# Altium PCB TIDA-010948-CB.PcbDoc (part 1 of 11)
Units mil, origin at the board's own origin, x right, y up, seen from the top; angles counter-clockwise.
Board outline 8100 x 8400 mil, 8 copper layers (L01 - TOP, L02 - GND, L03 - SIG, L04 - GND, L05 - PWR, L06 - SIG, L07 - GND, L08 - BOTTOM), stack 59.656 mil thick; 711 components, 572 nets, 2646 pads, 1325 vias.
Unrouted connection lines stored in the file: 988.
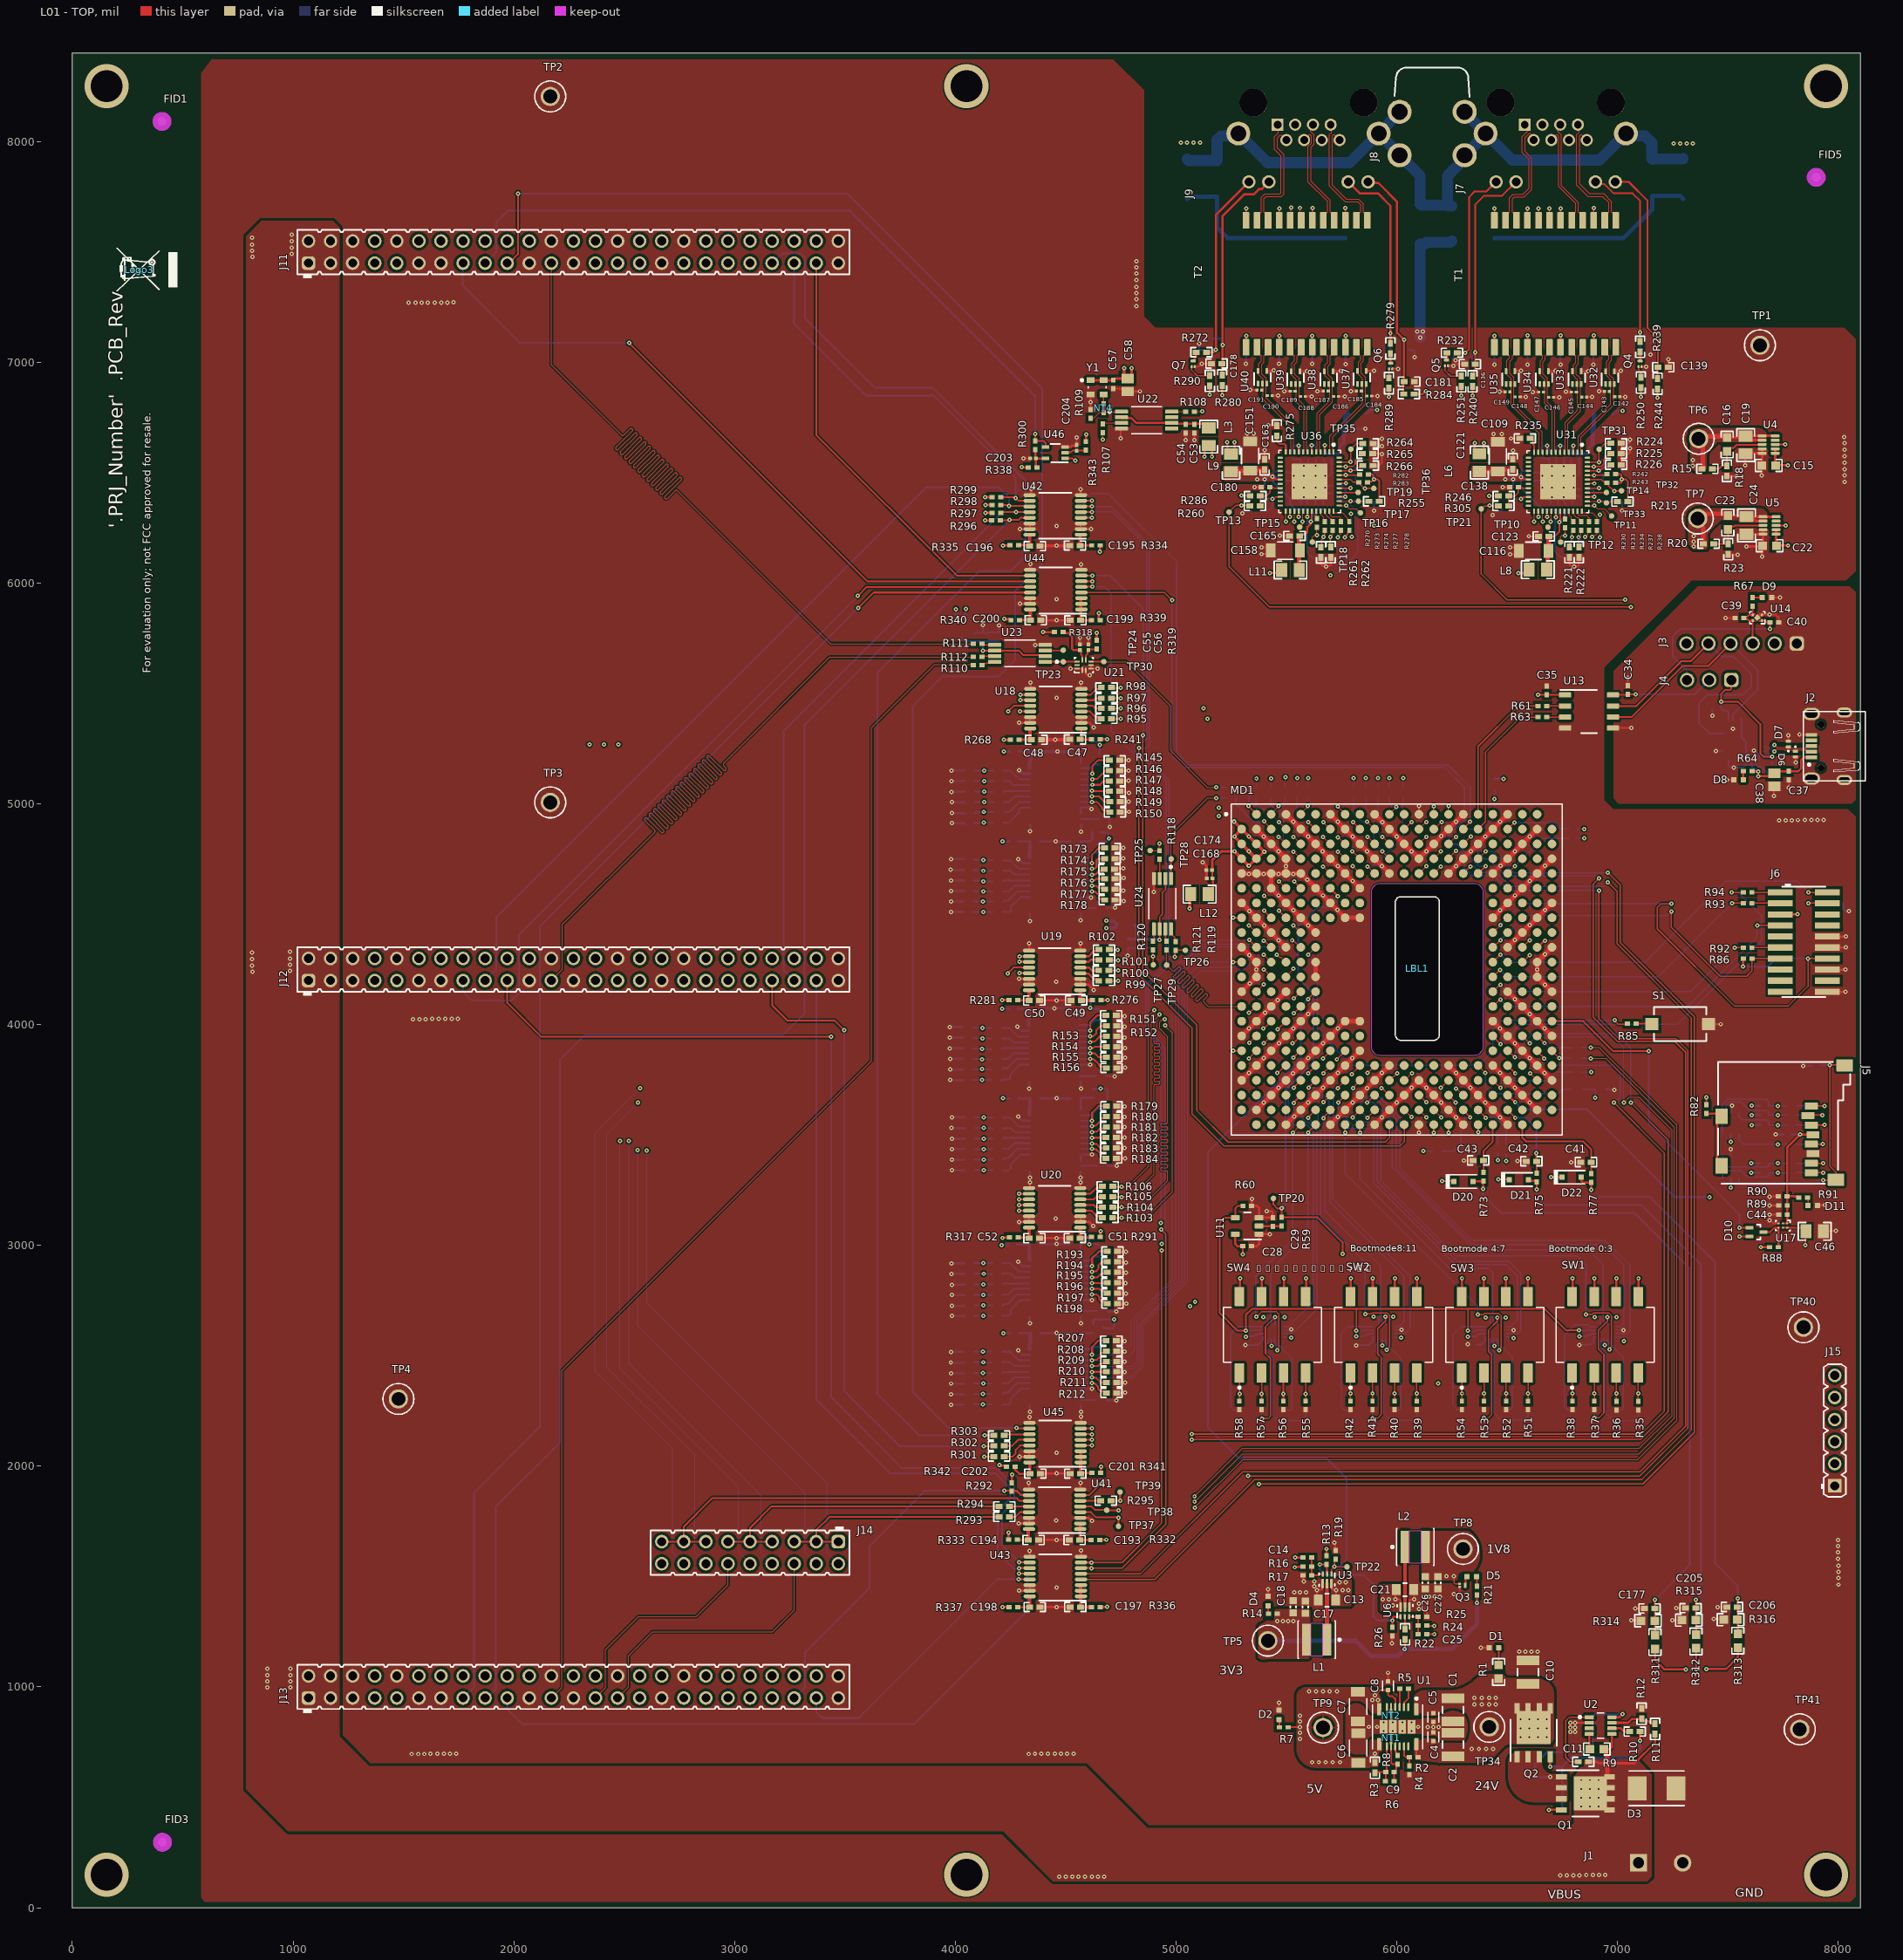
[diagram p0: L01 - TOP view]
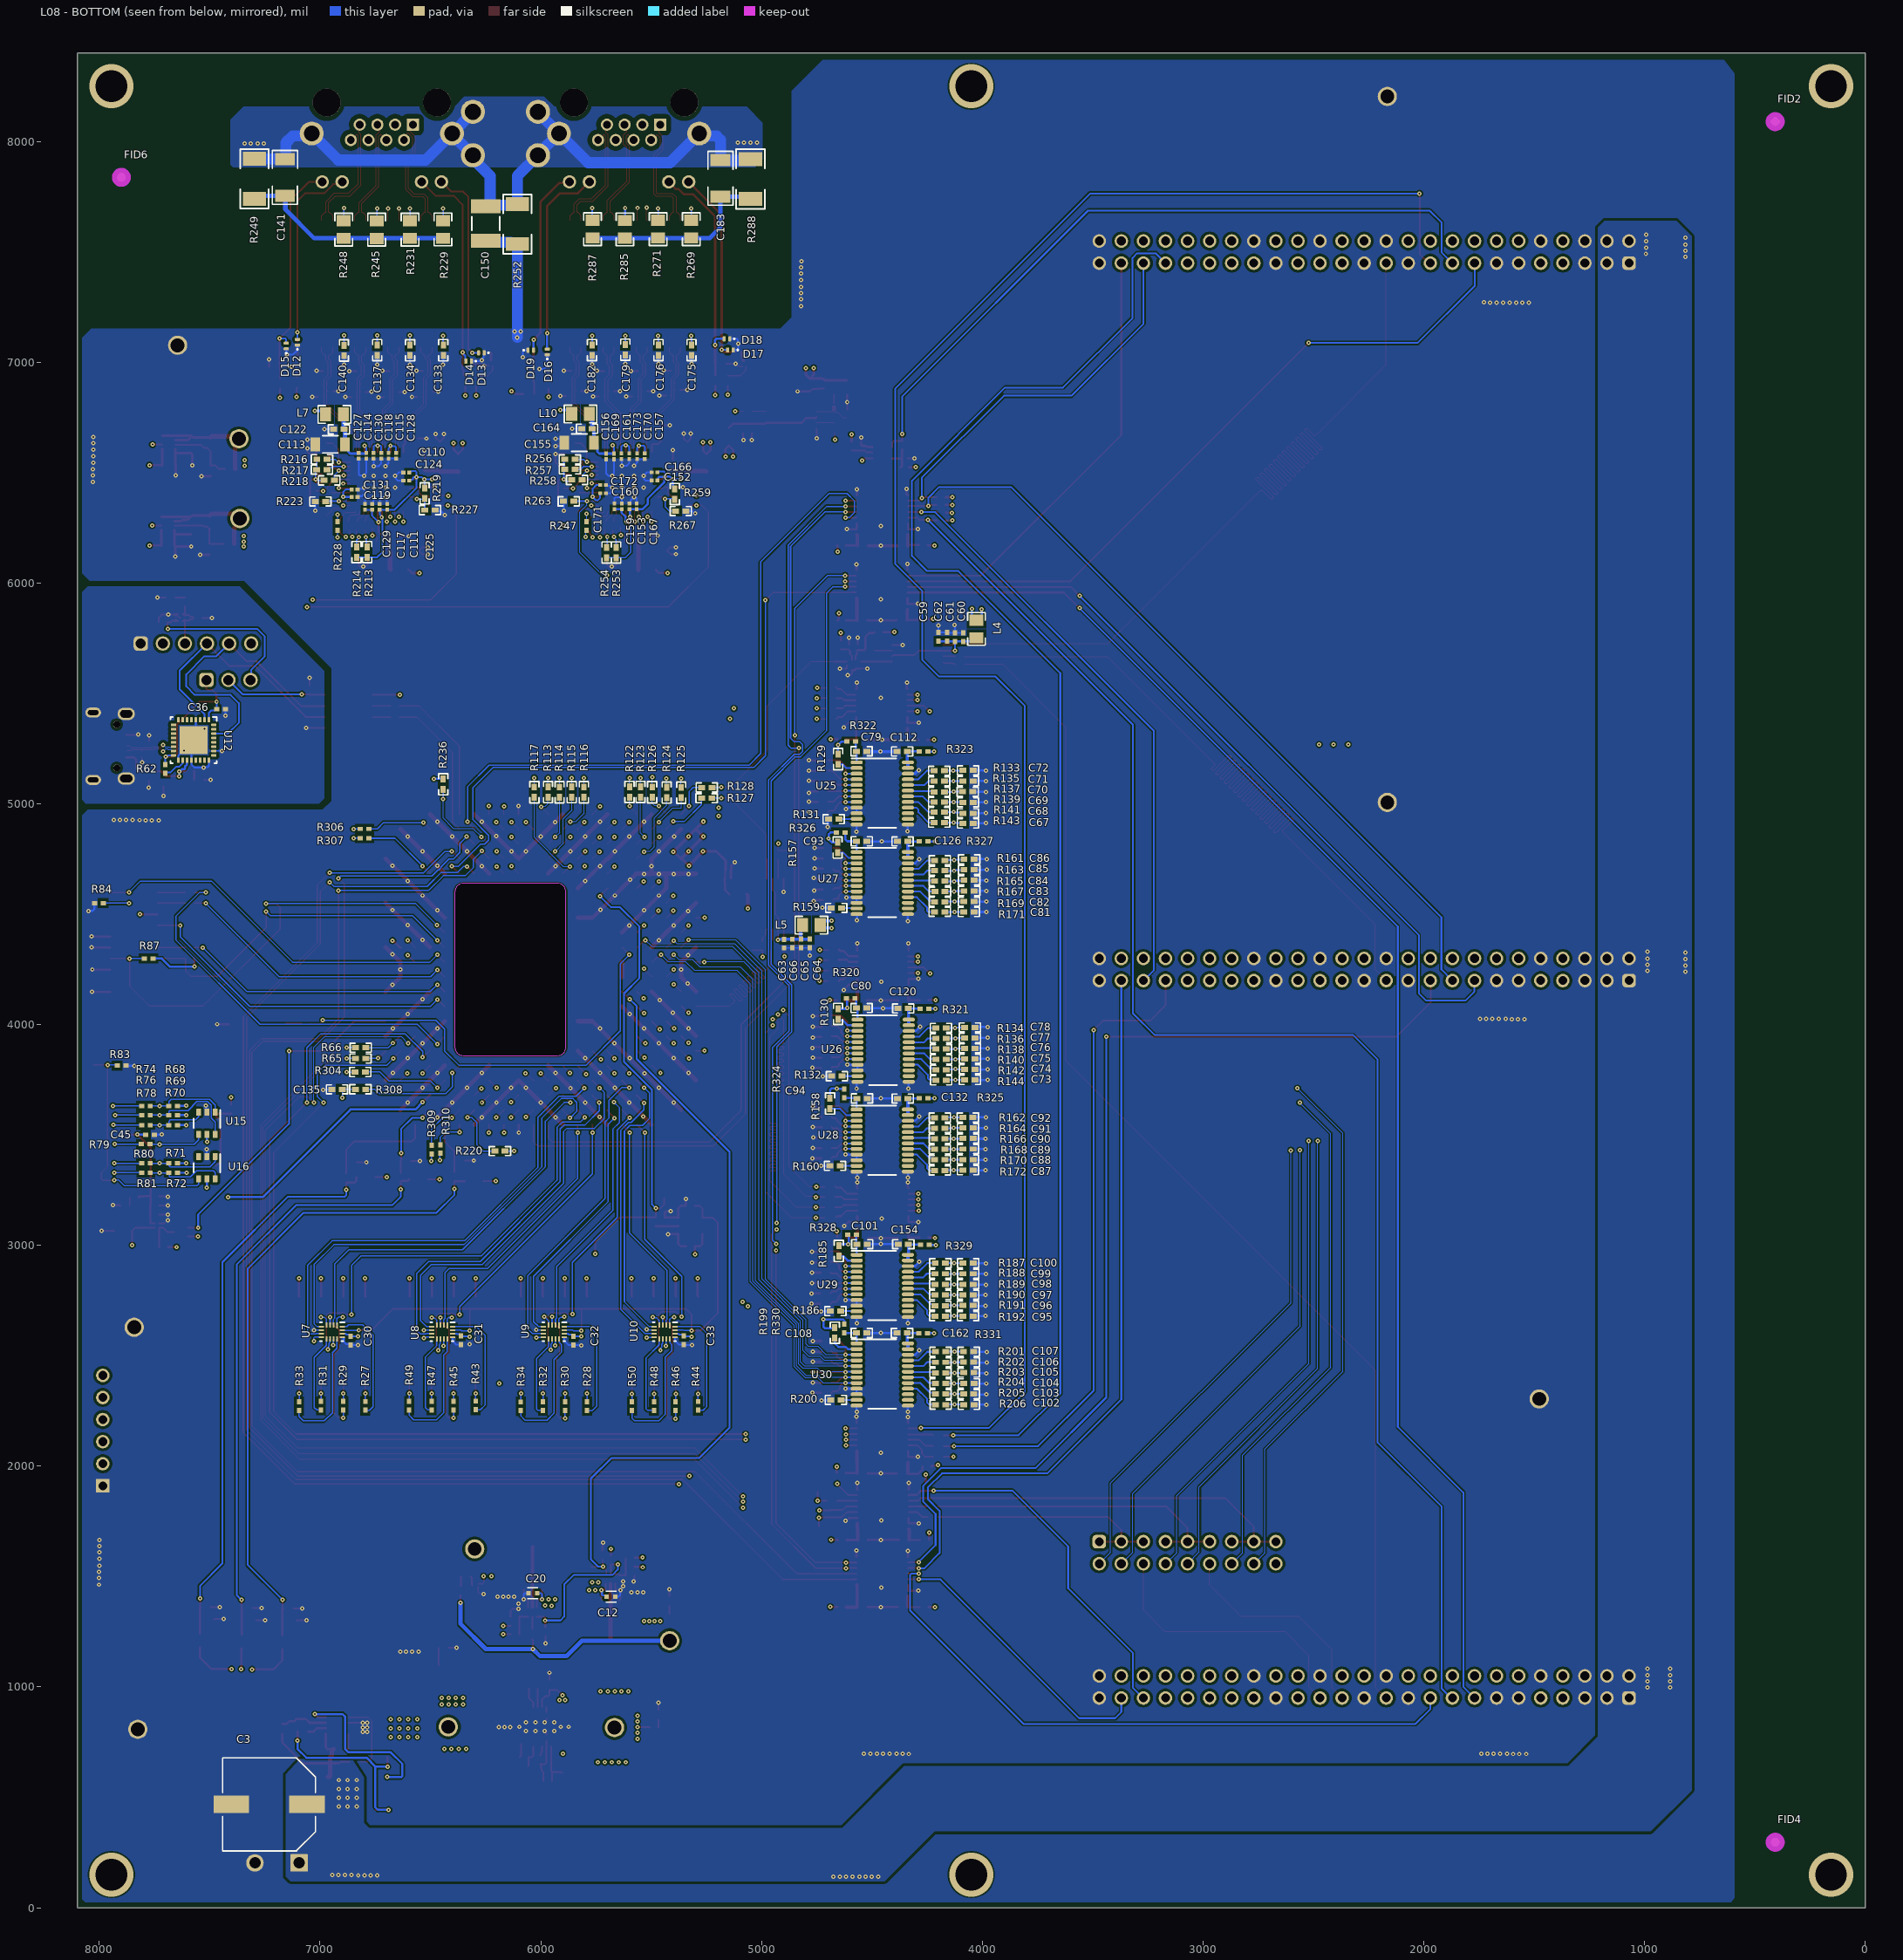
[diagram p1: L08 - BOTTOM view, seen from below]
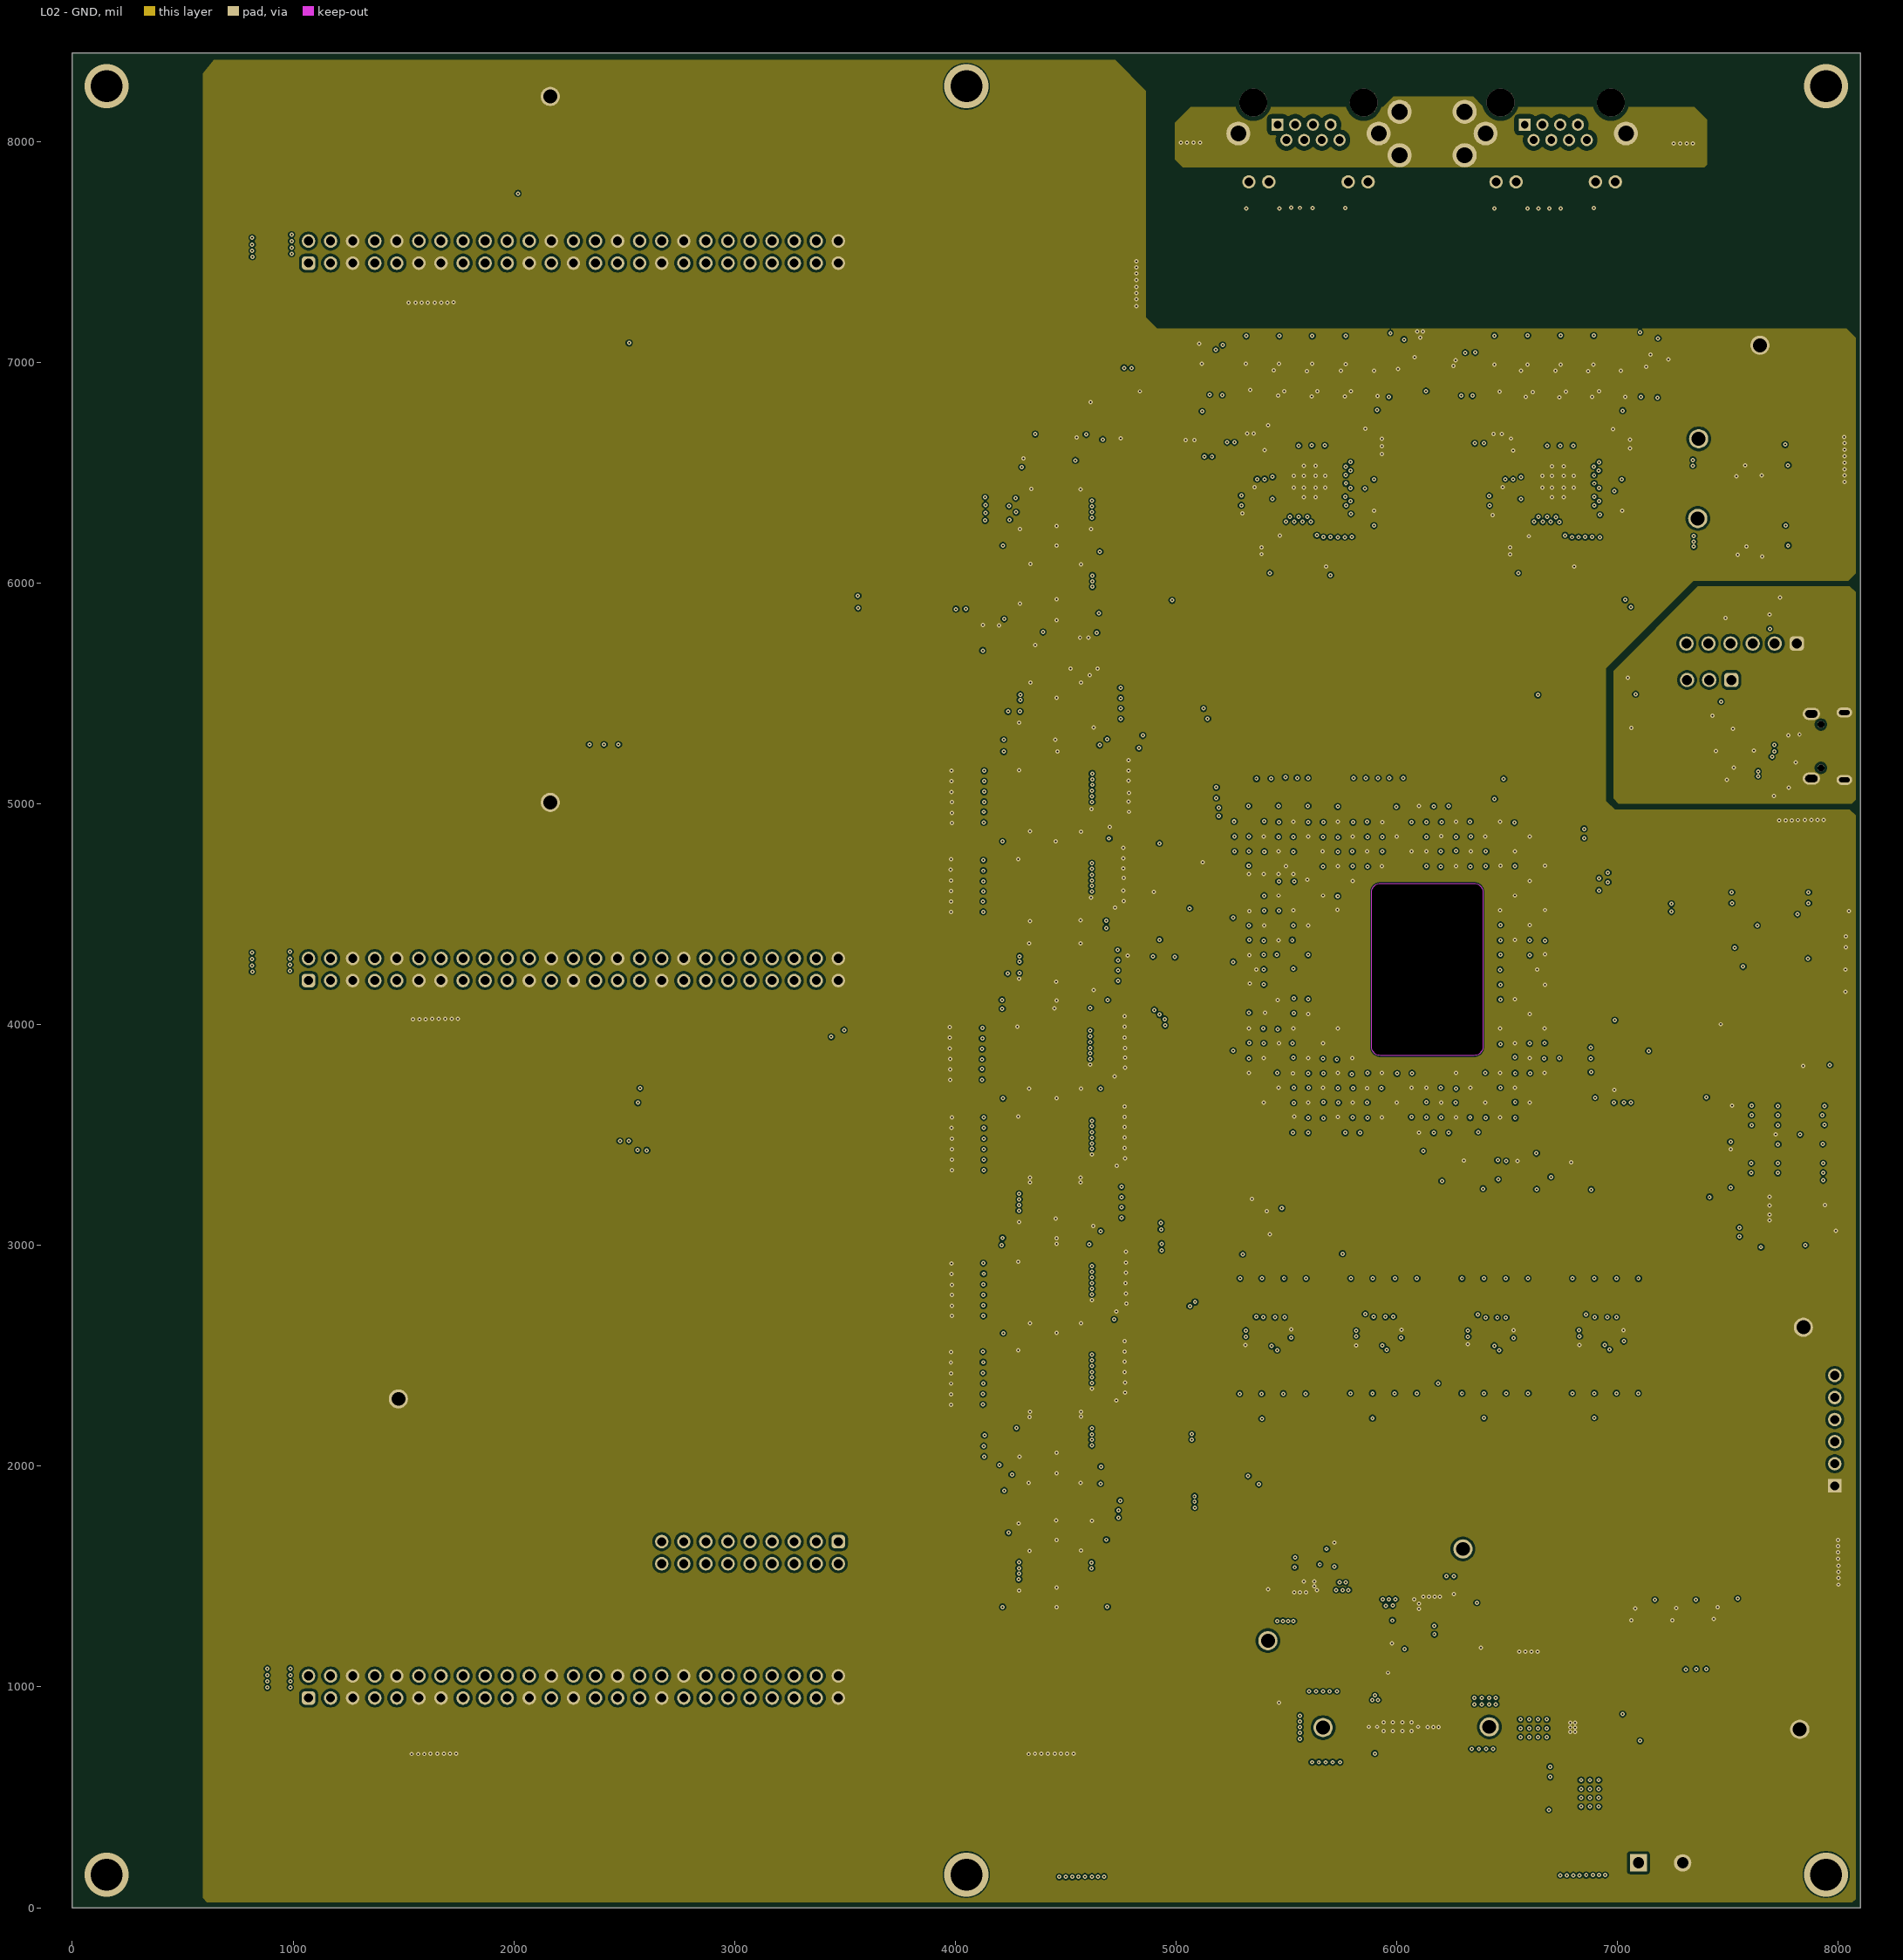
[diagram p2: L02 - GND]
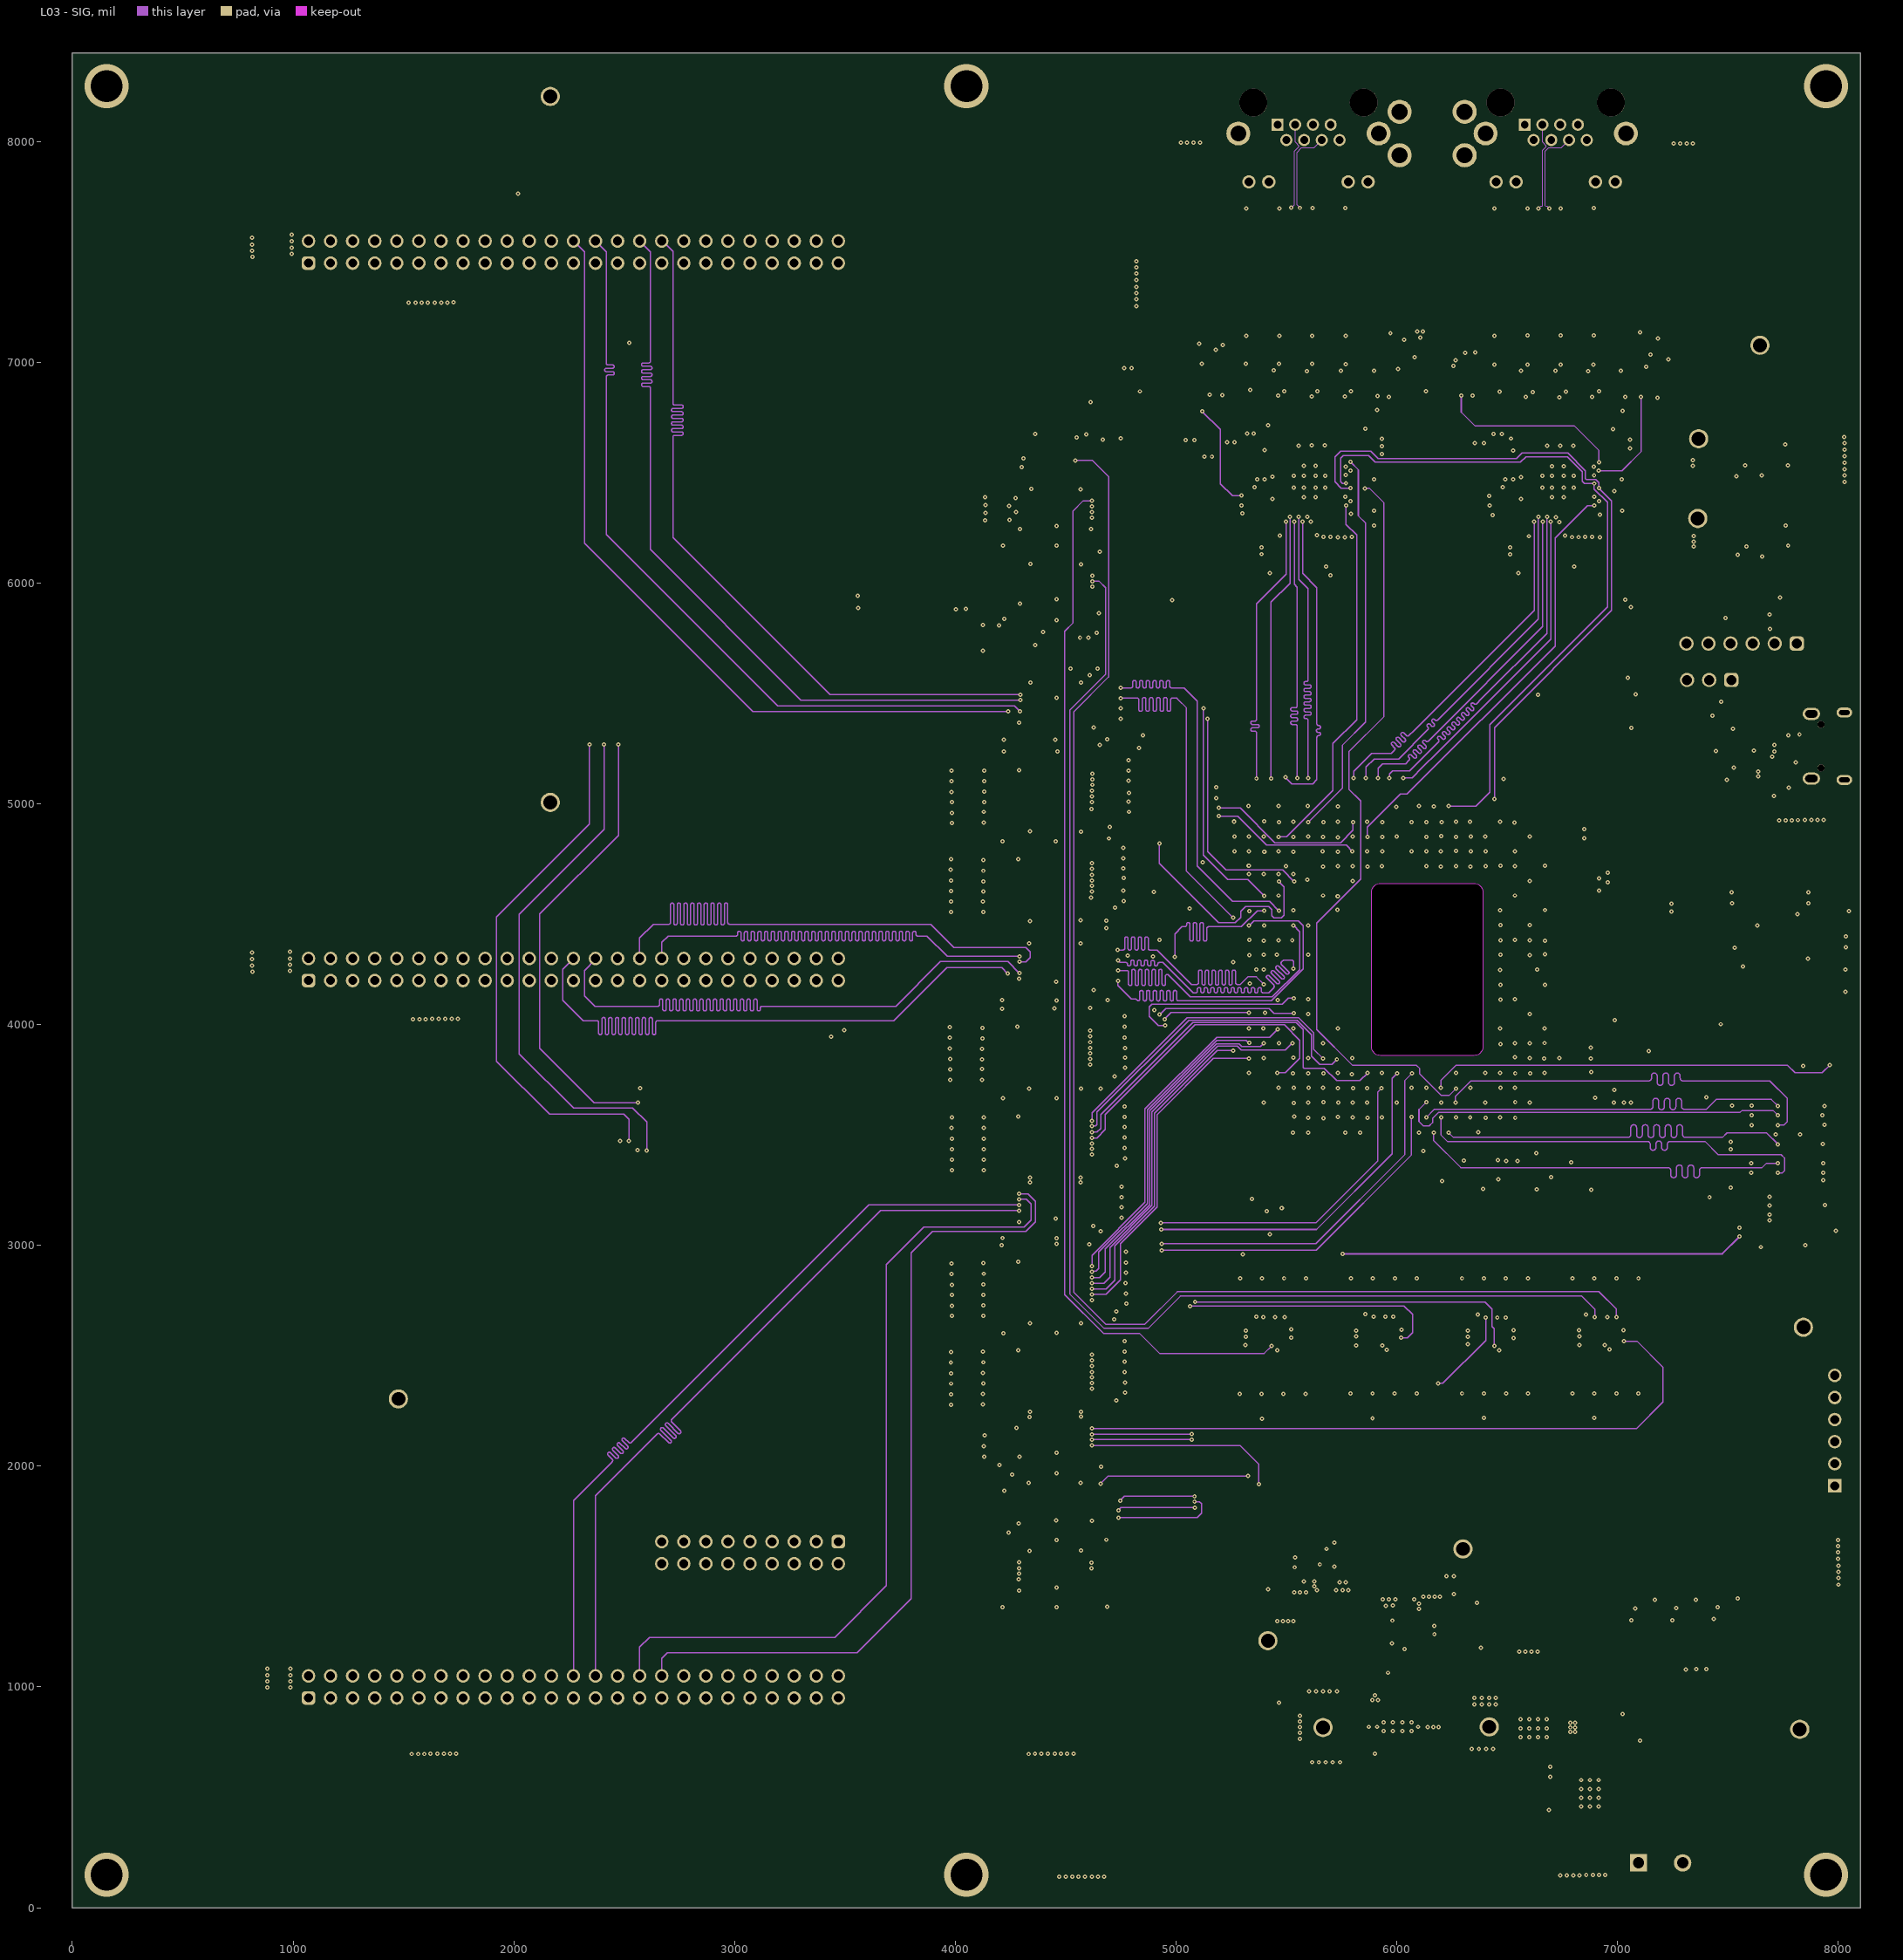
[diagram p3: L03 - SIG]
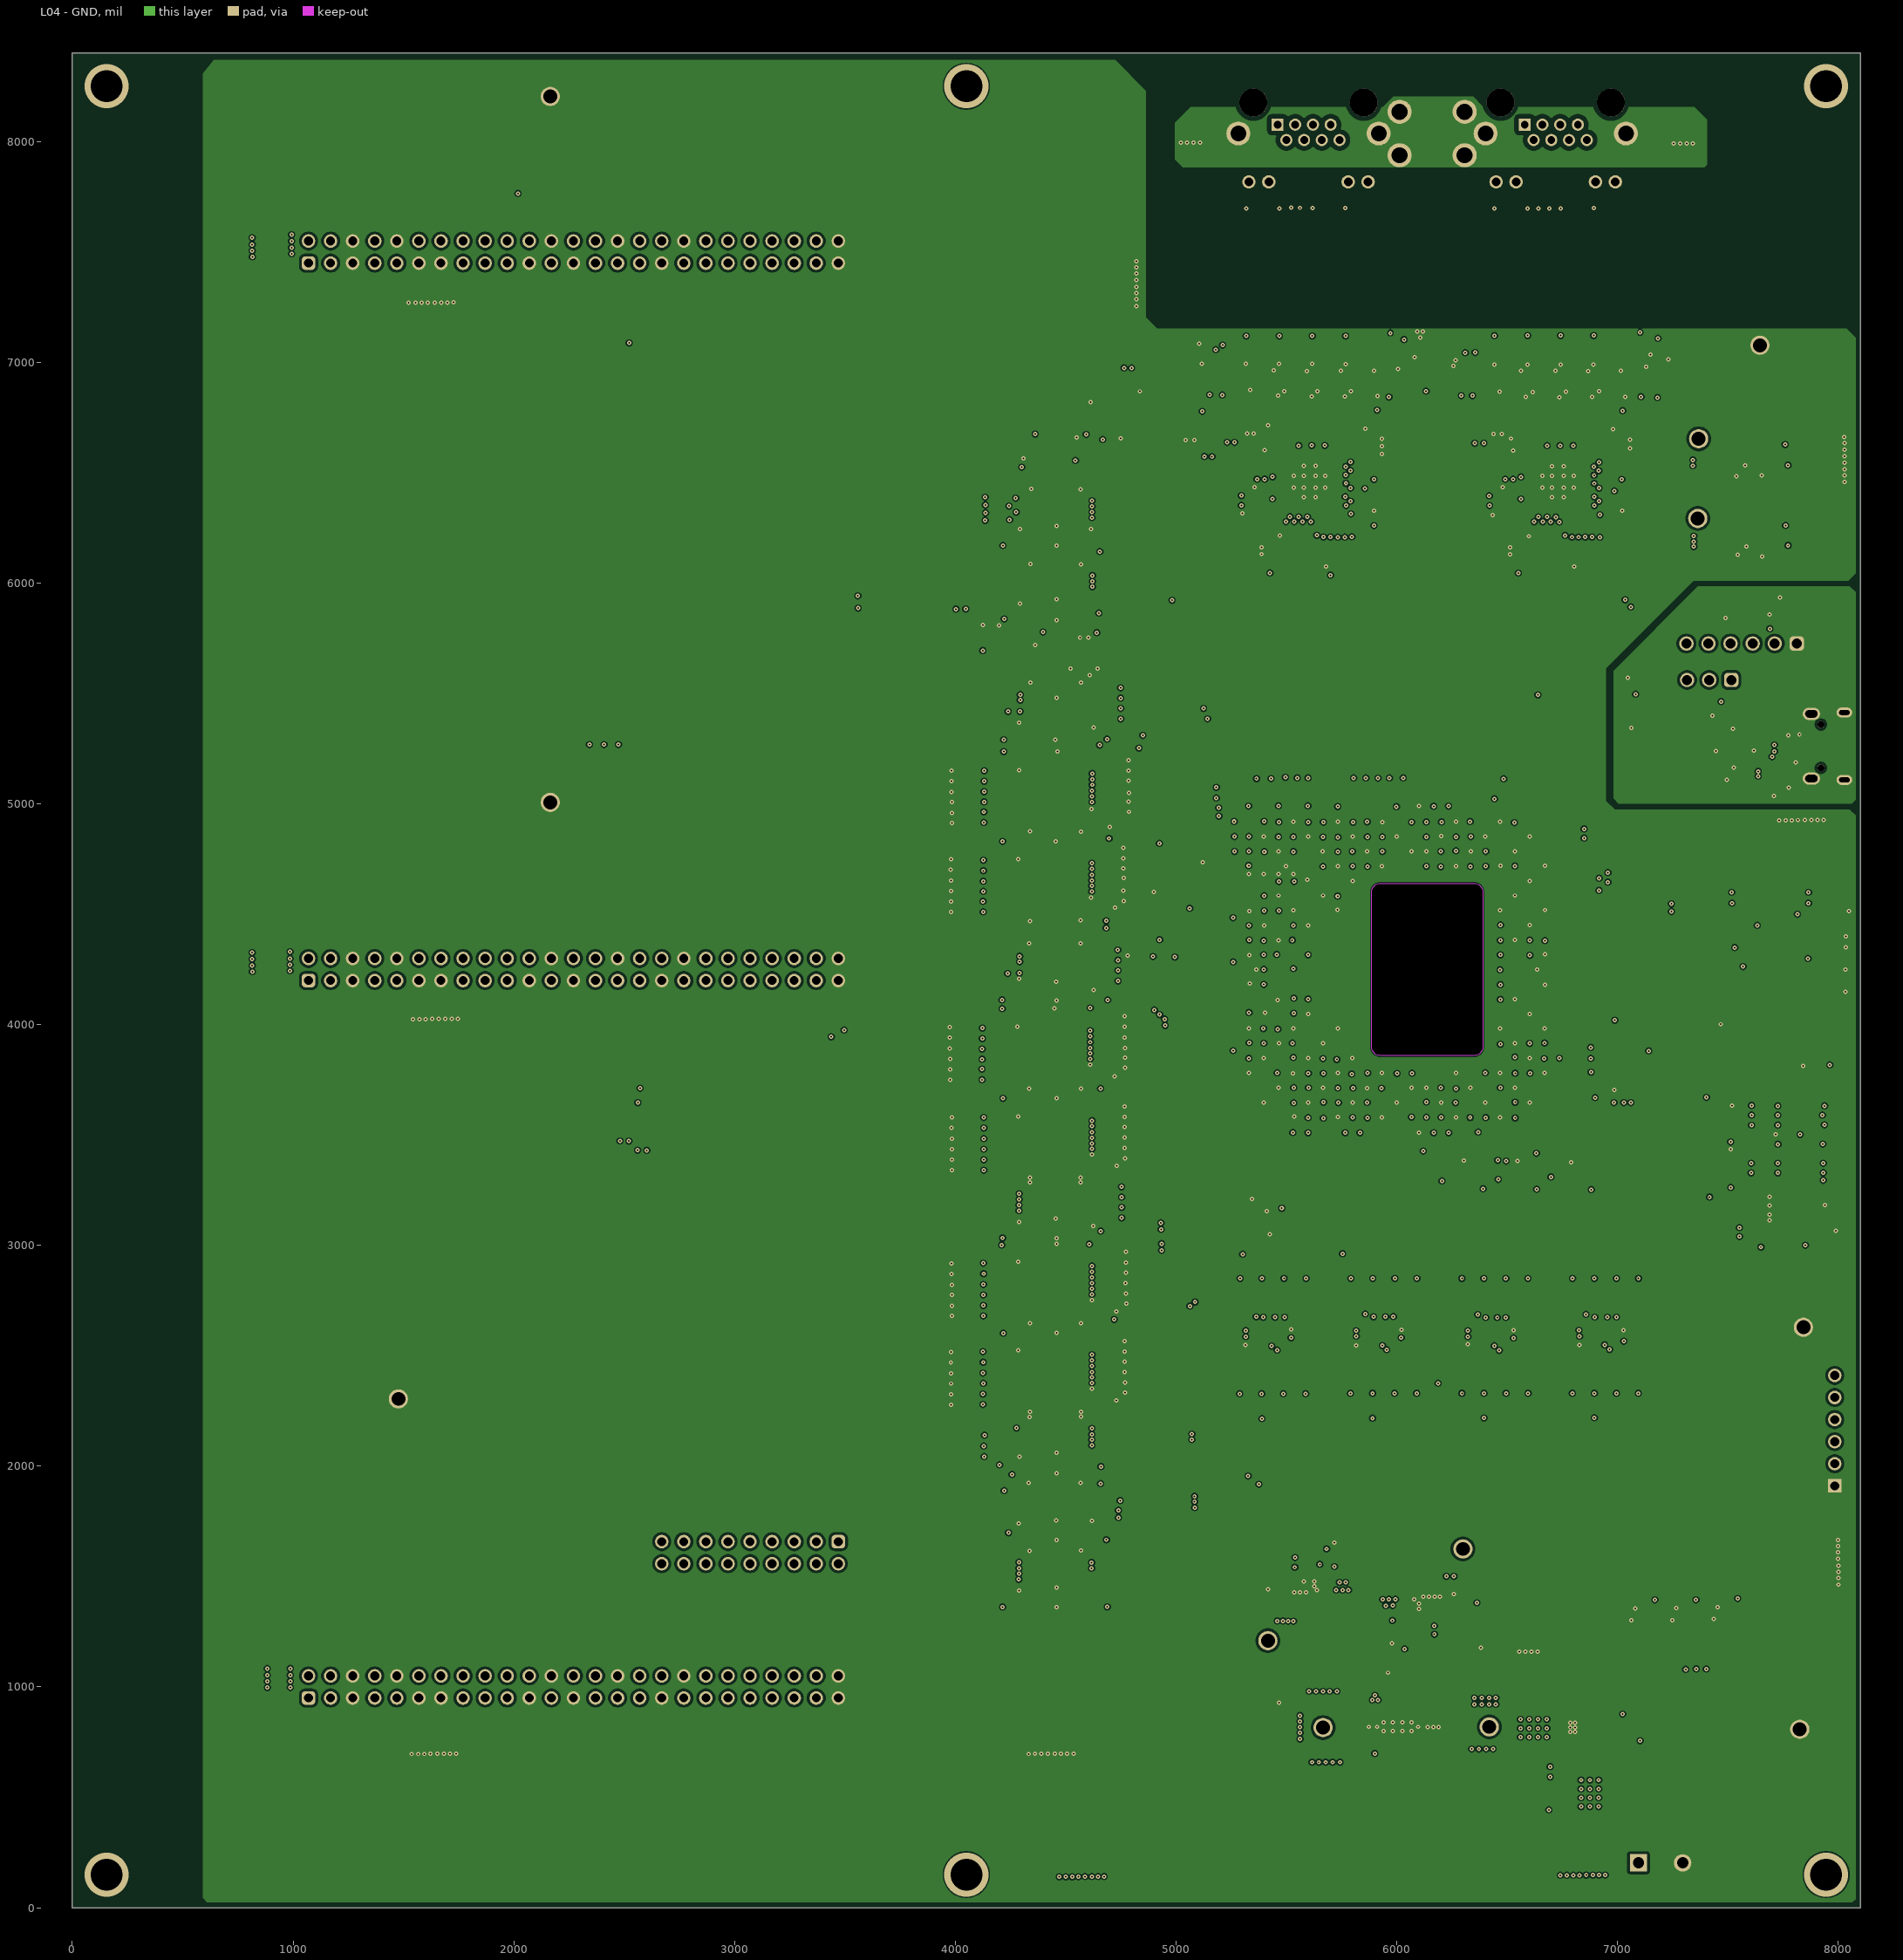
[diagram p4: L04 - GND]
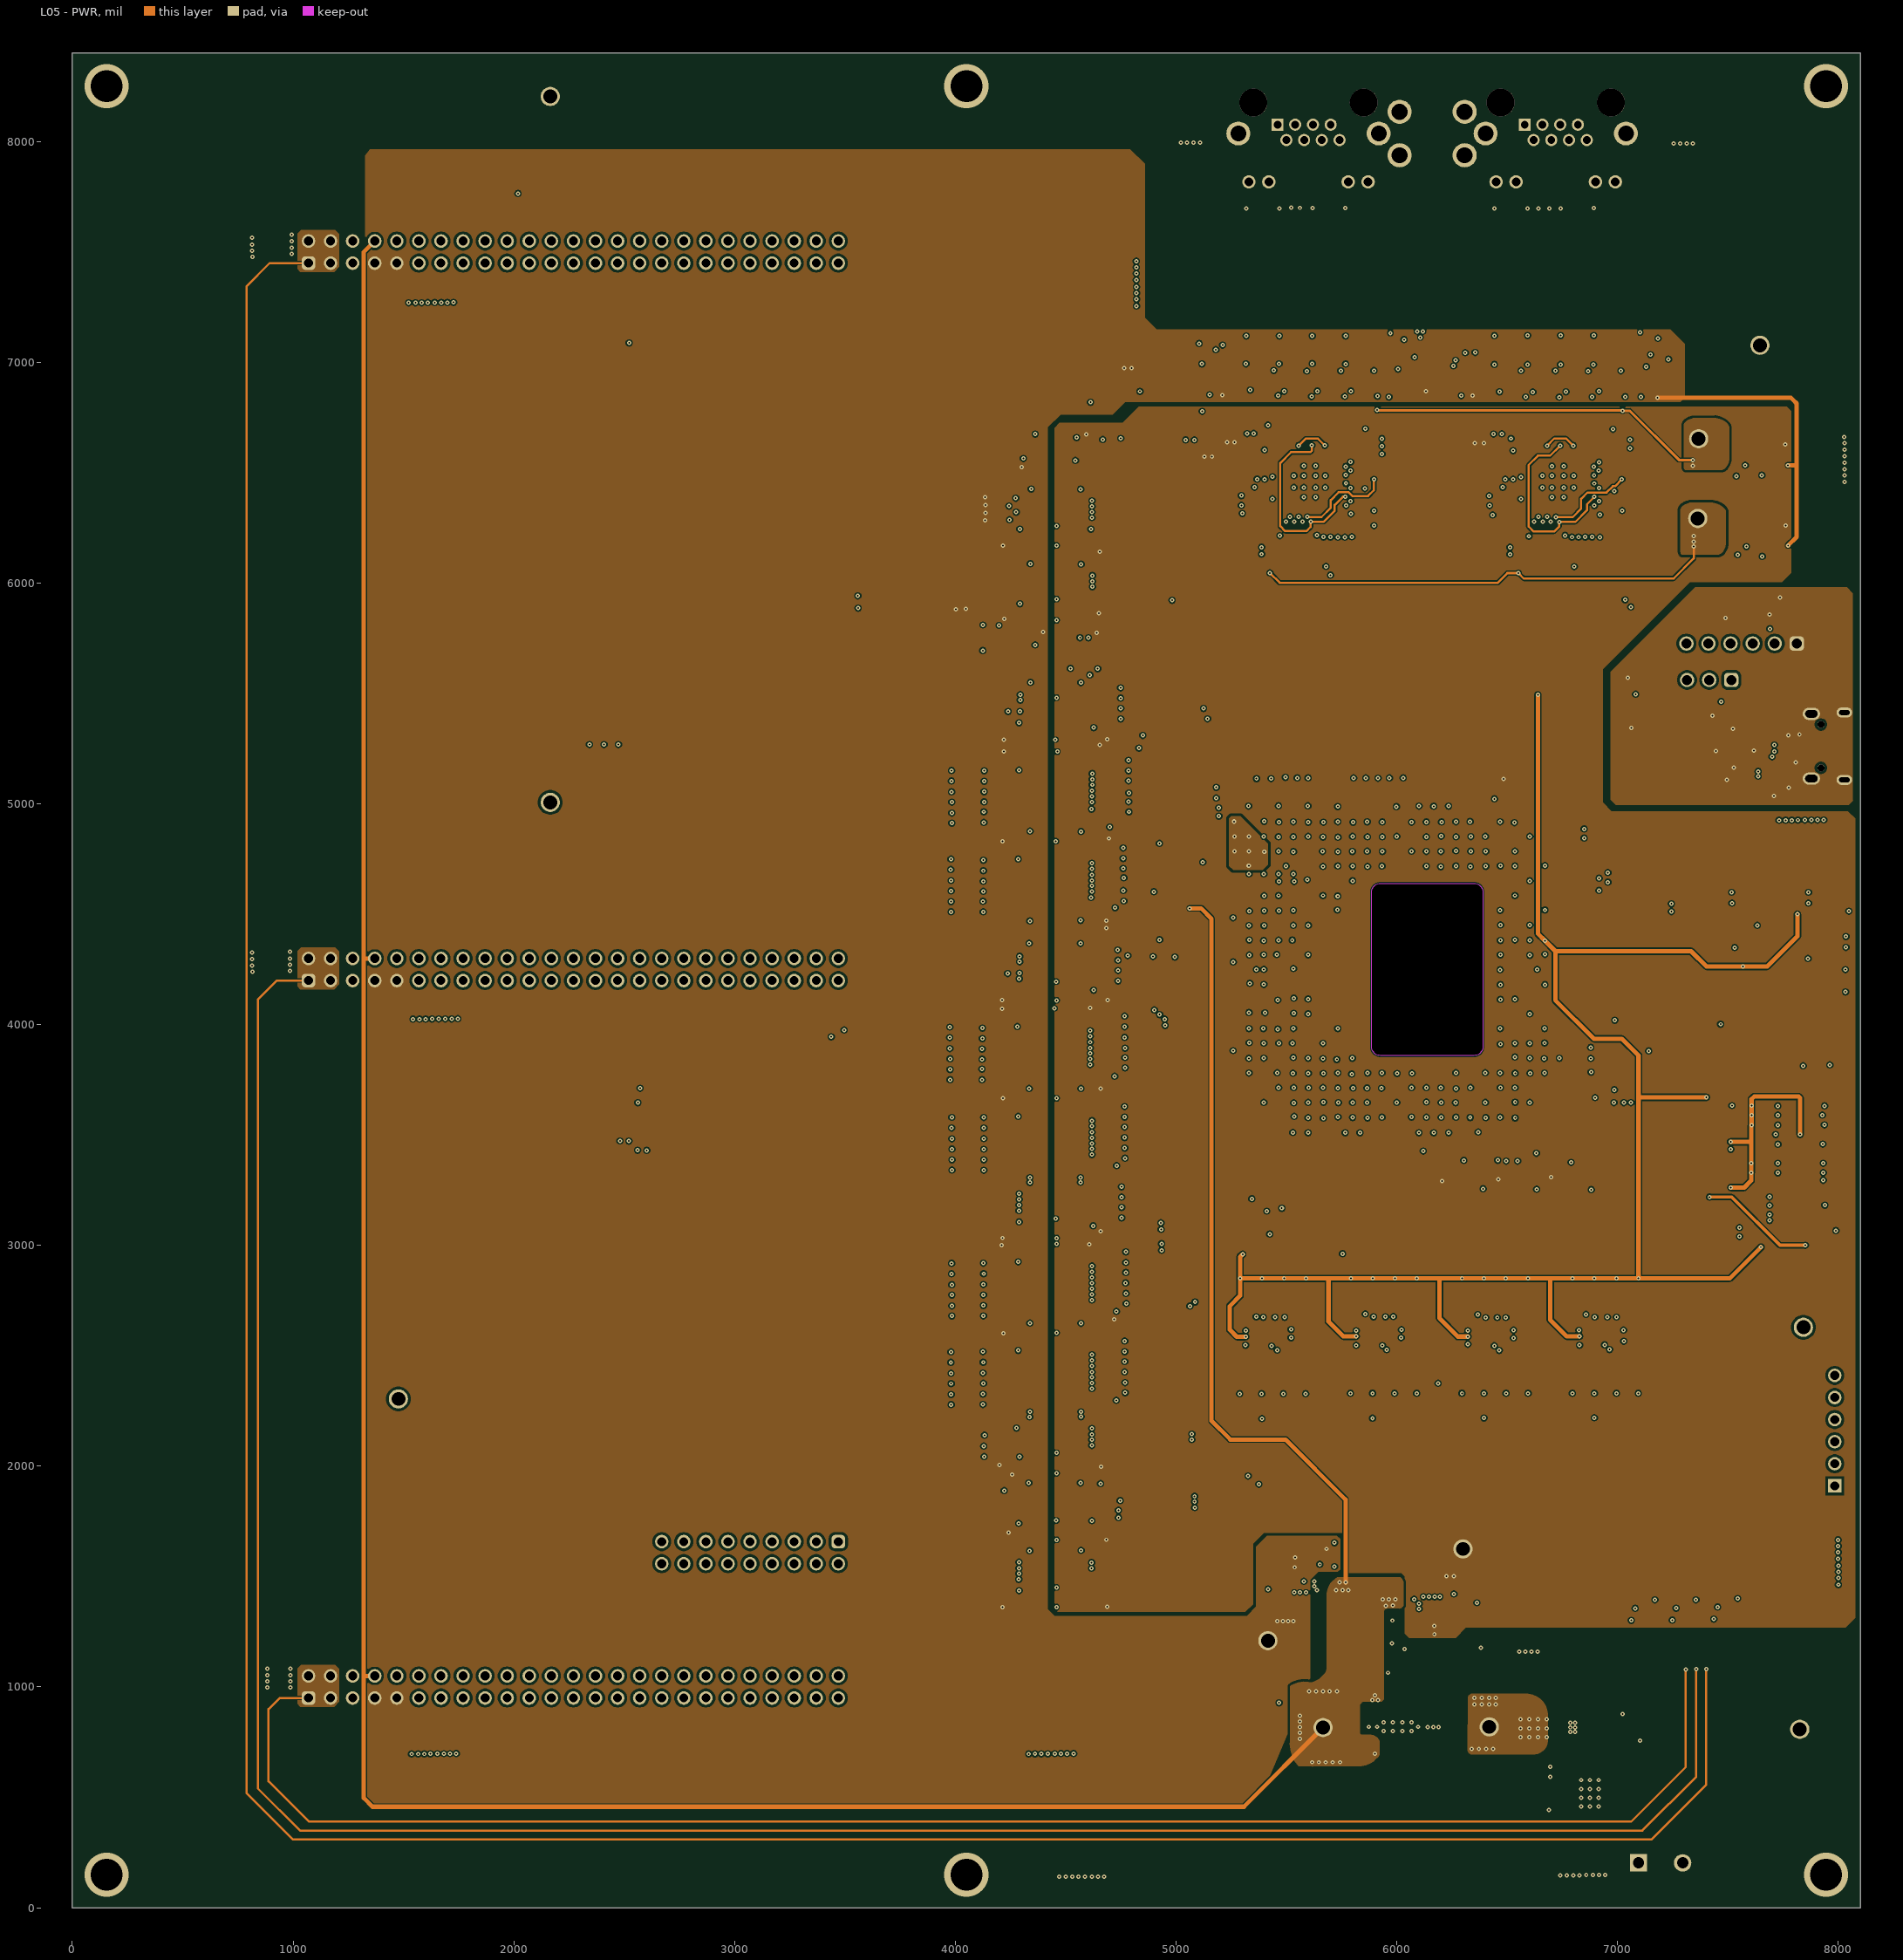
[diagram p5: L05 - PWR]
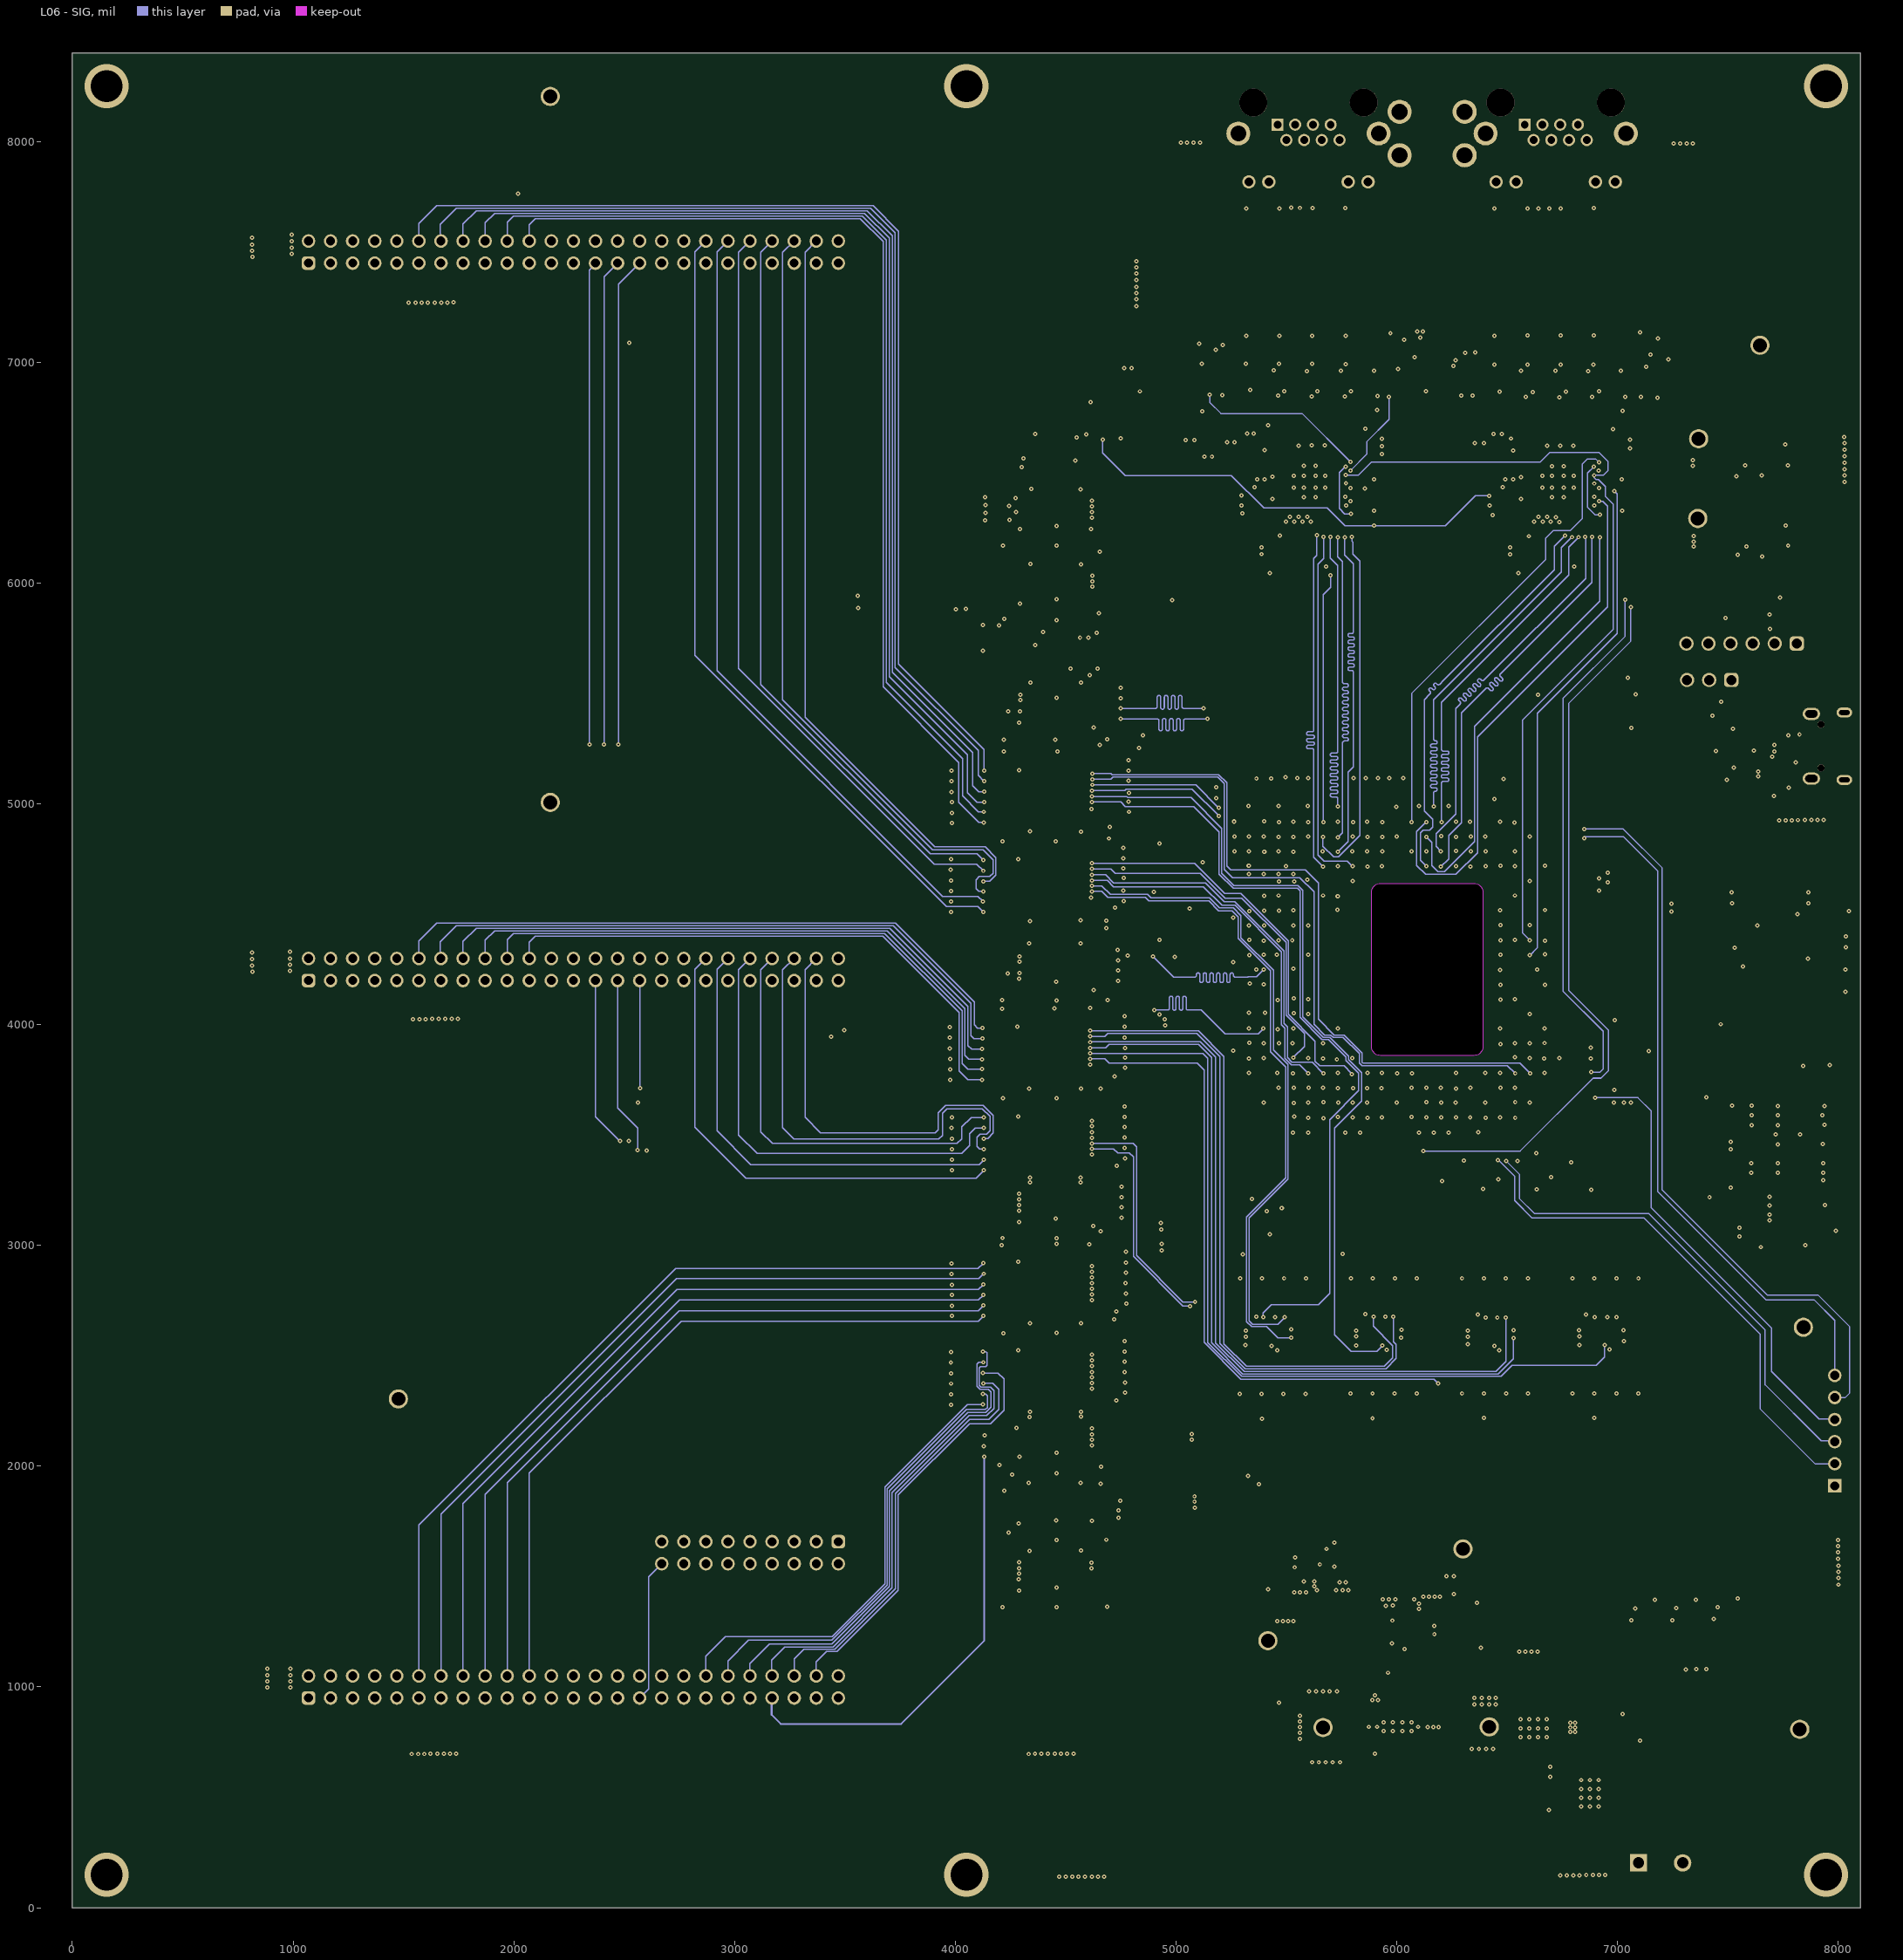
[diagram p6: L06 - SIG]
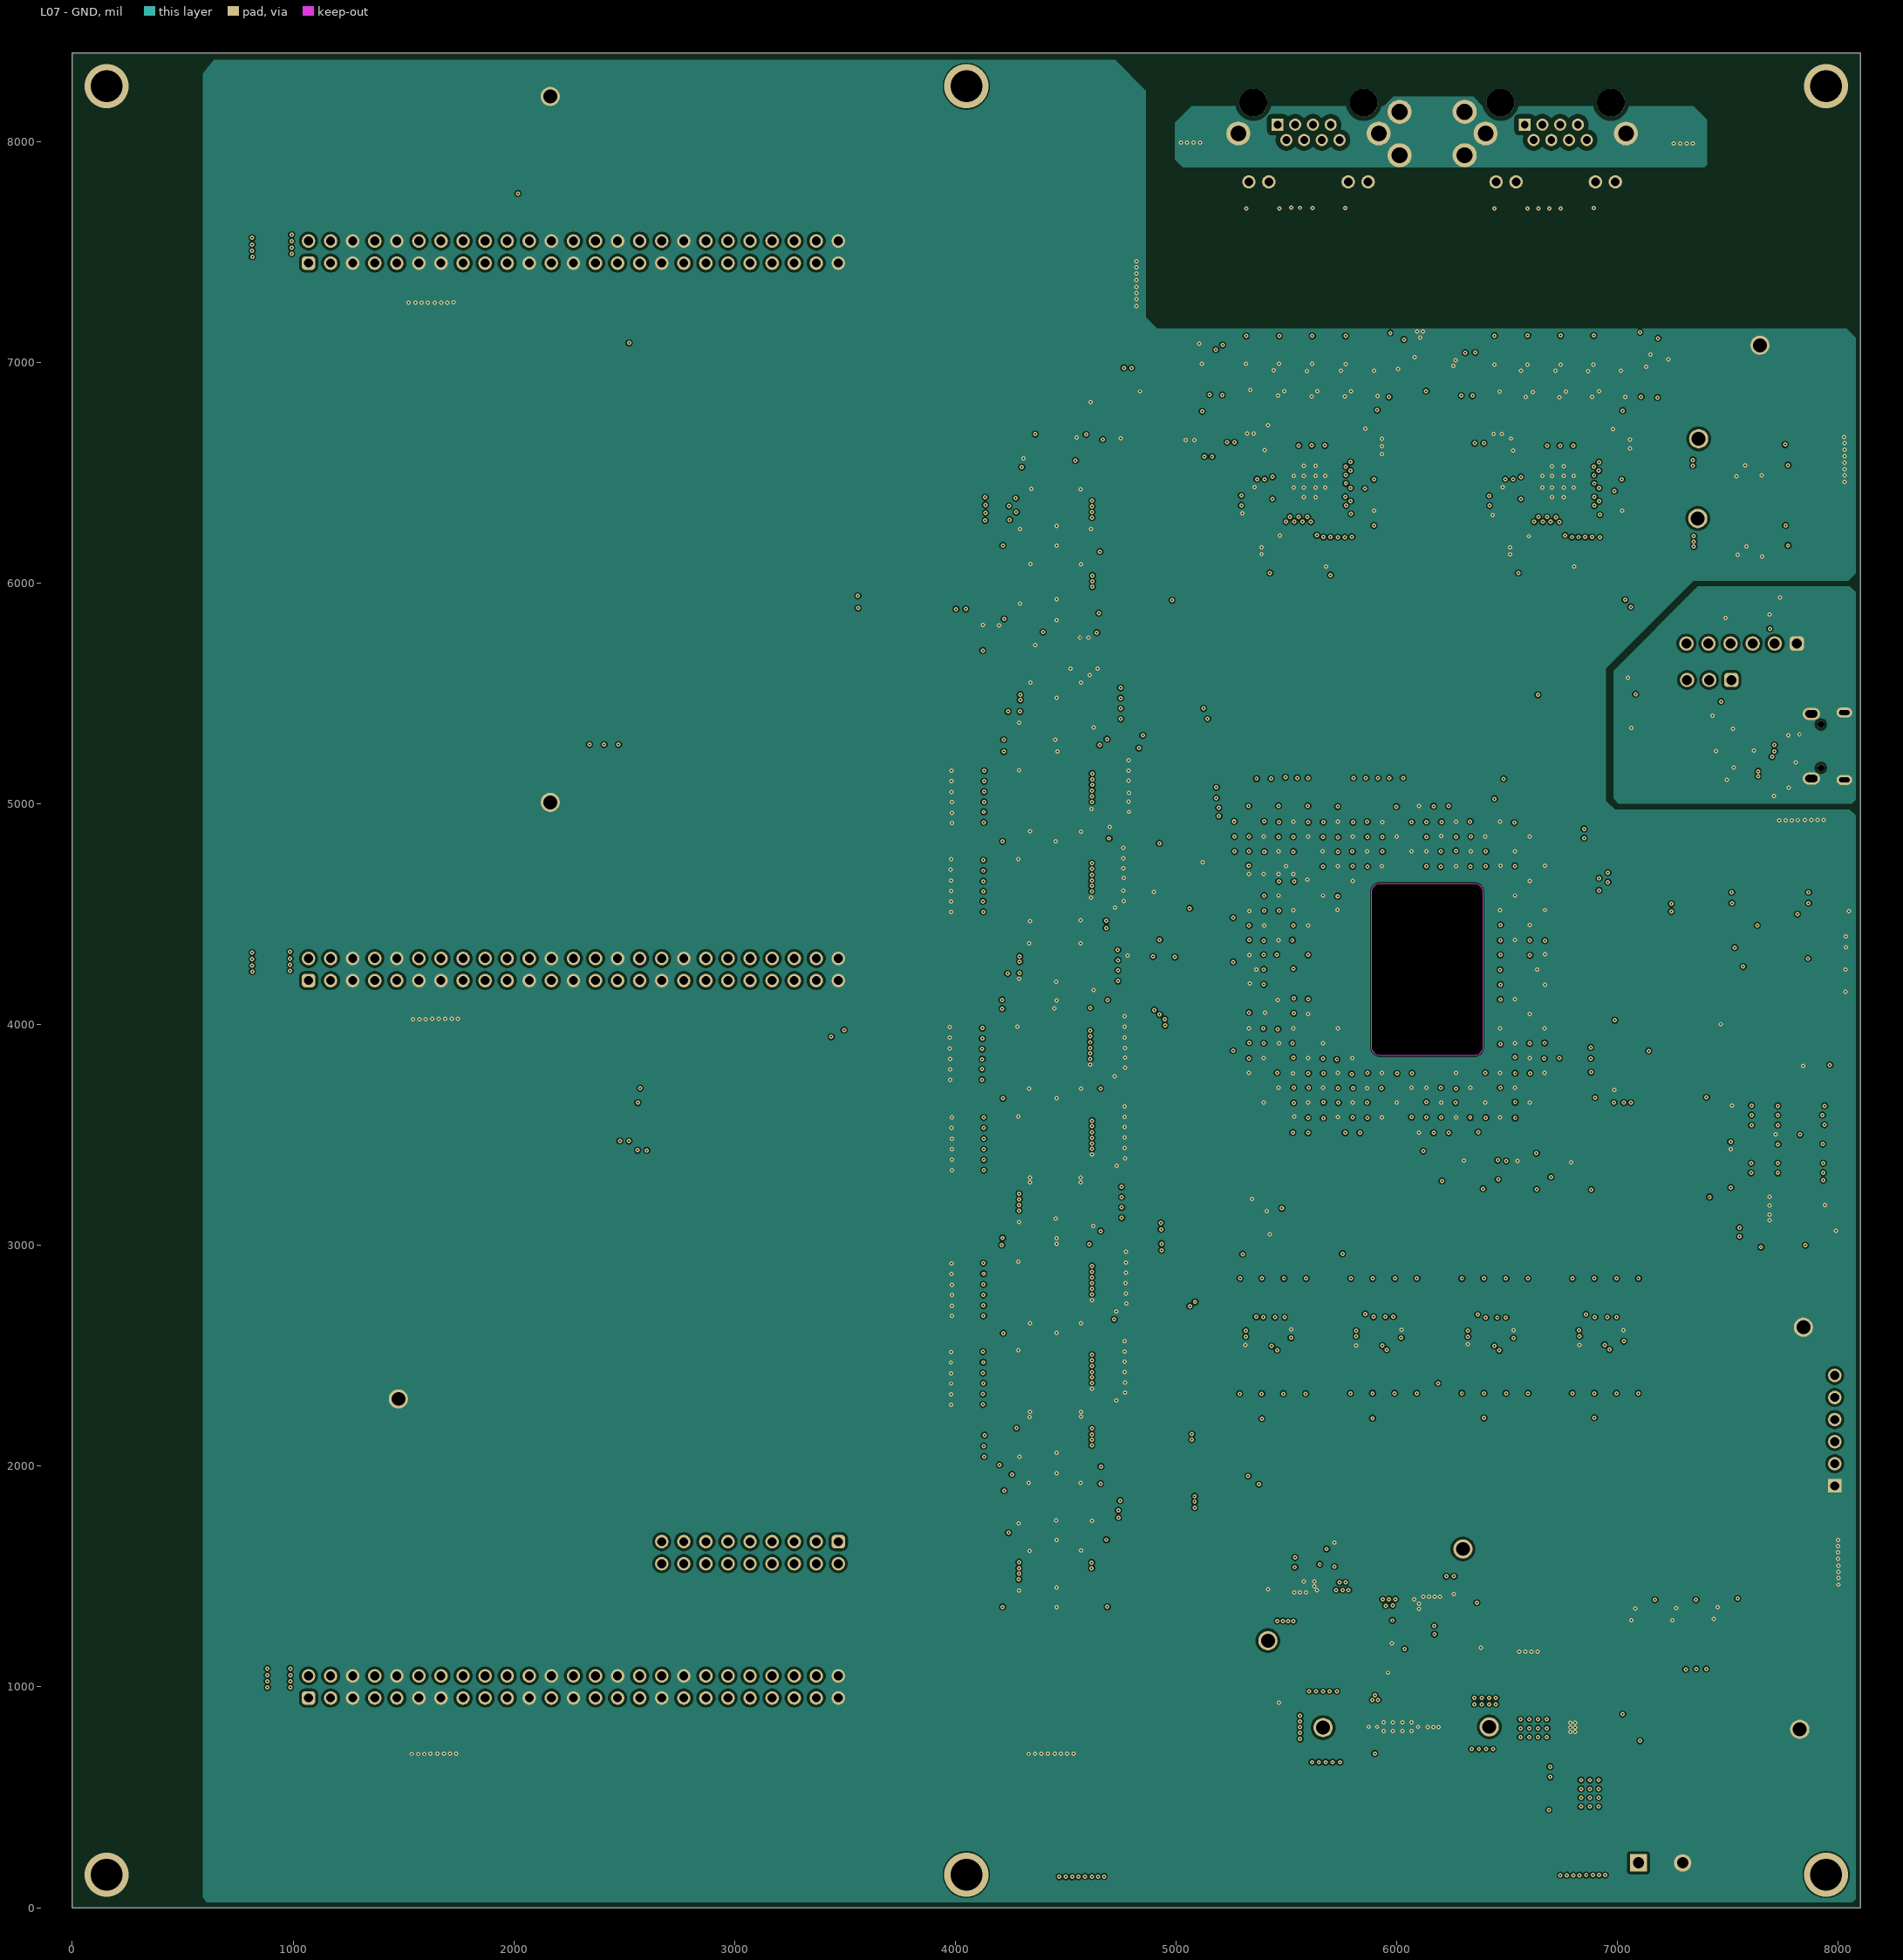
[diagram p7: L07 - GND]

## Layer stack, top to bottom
Top Solder: solder mask 0.9, Solder Resist, Dk 4.1
L01 - TOP: signal copper 1.378
Dielectric 1: prepreg 2.8, 1080-FR4 370, Dk 4.1
L02 - GND: signal copper 1.2
Dielectric 2: core 5, FR4 370, Dk 4.1
L03 - SIG: signal copper 1.2
Dielectric 3: prepreg 9.8, 1080-FR4 370 + 2116-FR4 370 + 1080-FR4 370, Dk 4.1
L04 - GND: signal copper 1.2
Dielectric 4: core 14.5, FR4 370, Dk 4.4
L05 - PWR: signal copper 1.2
Dielectric 5: prepreg 9.8, 1080-FR4 370 + 2116-FR4 370 + 1080-FR4 370, Dk 4.1
L06 - SIG: signal copper 1.2
Dielectric 6: core 5, FR4 370, Dk 4.1
L07 - GND: signal copper 1.2
Dielectric 7: prepreg 2.8, 1080-FR4 370, Dk 4.1
L08 - BOTTOM: signal copper 1.378
Bottom Solder: solder mask 0.9, Solder Resist, Dk 4.1

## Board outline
0,0 0,8400 8100,8400 8100,0

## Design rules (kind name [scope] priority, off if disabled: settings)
AcuteAngle [All] p1: minimum=4.50000000000000E+0001 checktracksonly=FALSE
AssemblyTestPointUsage [All] p1: valid=2
BoardOutlineClearance BoardOutlineClearance_MountingHoles [OnCopper and InComponentClass('Mounting Holes')] p1: gap=39.37 ignorepadtopadclearanceinfootprint=FALSE
BoardOutlineClearance BoardOutlineClearance_Poly [OnCopper and IsPoly] p2: gap=21.65 ignorepadtopadclearanceinfootprint=FALSE
BoardOutlineClearance [OnCopper and Not InComponentClass('Logo') and not InComponentClass('FiducialMark') and not InRegion(1000,500,4000,800) and not InPoly   and not IsKeepOut] p3: gap=75 ignorepadtopadclearanceinfootprint=FALSE except(18.5: THPad-OutlineEdge; 19.68: Track-OutlineEdge Poly-OutlineEdge; 23.23: THPad-CutoutEdge; 24: Track-CutoutEdge SMDPad-OutlineEdge SMDPad-CutoutEdge Via-OutlineEdge Via-CutoutEdge Fill-OutlineEdge Fill-CutoutEdge Poly-CutoutEdge Region-OutlineEdge Text-OutlineEdge Text-CutoutEdge)
Clearance Clearance_PE-to-others [InNet('EARTH_GND') vs All and not InNetClass('PE-side')] p1: gap=20 ignorepadtopadclearanceinfootprint=TRUE
Clearance Clearance_CLKs-to-others [InNetClass('CLKs') vs All  and not (InNetClass('PWR') and IsTrack)] p2 off: gap=5.9 ignorepadtopadclearanceinfootprint=TRUE except(6: Arc-THPad Arc-Via Arc-Fill Arc-Poly Arc-Region Track-THPad Track-Via Track-Fill Track-Region SMDPad-Via THPad-Fill THPad-Poly THPad-Region; 7.99: Track-SMDPad; 8: Arc-SMDPad SMDPad-SMDPad; 10: Arc-Hole Track-Hole SMDPad-THPad SMDPad-Hole THPad-THPad THPad-Via Via-Hole Fill-Hole Poly-Hole Region-Hole; 12.99: Track-Track; 14: Arc-Arc Arc-Track; 20: Track-Poly THPad-Hole)
Clearance Clearance_DiffPairs-to-others [InAnyDifferentialPair vs All and not InAnyDifferentialPair] p3: gap=5.9 ignorepadtopadclearanceinfootprint=TRUE except(6: Arc-THPad Arc-Via Arc-Fill Arc-Poly Arc-Region Track-THPad Track-Fill Track-Region SMDPad-Via THPad-Fill THPad-Poly THPad-Region; 8: Arc-SMDPad Track-SMDPad Track-Via SMDPad-SMDPad; 10: Arc-Hole Track-Hole SMDPad-THPad SMDPad-Hole THPad-THPad THPad-Via Via-Hole Fill-Hole Poly-Hole Region-Hole; 12: Track-Track; 14: Arc-Arc Arc-Track; 20: Track-Poly THPad-Hole)
Clearance Clearance_Keepouts [((IsTrack Or IsArc) And Not InPoly) And IsFree and IsKeepOut vs ((IsTrack Or IsArc) And Not InPoly) And IsFree and IsKeepOut] p4: gap=0 ignorepadtopadclearanceinfootprint=FALSE
Clearance Clearance_NTPHs [(ObjectKind = 'Pad') And (Layer = 'MultiLayer') And (PadIsPlated = 'False')] p5 off: gap=19.68 ignorepadtopadclearanceinfootprint=FALSE
Clearance Clearance_Poly [InPolygon] p6: gap=5.91 ignorepadtopadclearanceinfootprint=TRUE except(11.81: SMDPad-Poly THPad-Poly Poly-Poly)
Clearance Clearance_FiducialMark [IsKeepOut and InComponentClass('FiducialMark') vs IsPad and InComponentClass('FiducialMark')] p7: gap=0 ignorepadtopadclearanceinfootprint=FALSE
Clearance [All and not HasFootprint('DQN0004A')] p8: gap=5 ignorepadtopadclearanceinfootprint=TRUE except(10: Poly-Poly)
ComponentClearance ComponentClearance_MountingHoles_FiducialMarks [InComponentClass('Mounting Holes') vs InComponentClass('FiducialMark')] p1: gap=50 collisioncheckmode=3 verticalgap=10 showdistances=FALSE
ComponentClearance ComponentClearance_Shunt [InComponentClass('Header') vs InComponentClass('Shunt')] p2: gap=0 collisioncheckmode=3 verticalgap=0 showdistances=FALSE
ComponentClearance ComponentClearance_Logo [InComponentClass('Logo')] p3: gap=30 collisioncheckmode=3 verticalgap=10 showdistances=FALSE
ComponentClearance ComponentClearance_ScrewToNut [(HasFootprint('NY PMS 440 0025 PH')) vs (HasFootprint('Keystone_1902C'))] p4: gap=5 collisioncheckmode=3 verticalgap=10 showdistances=FALSE
ComponentClearance ComponentClearance_MountingHoles [InComponentClass('Mounting Holes')] p5: gap=100 collisioncheckmode=3 verticalgap=100000 showdistances=FALSE
ComponentClearance ComponentClearance_Net_Tie [InComponent('NT*')] p6: gap=0 collisioncheckmode=3 verticalgap=0 showdistances=FALSE
ComponentClearance ComponentClearance_SmallPassives [HasFootprint('0201*') or HasFootprint('0402*') or HasFootprint('0508') or HasFootprint('0603*') or HasFootprint('0612') or HasFootprint('0805*') or HasFootprint('0815*') or HasFootprint('0830*') or HasFootprint('1206*') or HasFootprint('1210*') or HasFootprint('1808*') or HasFootprint('1812*') or HasFootprint('1825*') or HasFootprint('2010*') or HasFootprint('2220*') or HasFootprint('2225*') or HasFootprint('2512*') or HasFootprint('2728*') or HasFootprint('3518*') vs HasFootprint('0201*') or HasFootprint('0402*') or HasFootprint('0508') or HasFootprint('0603*') or HasFootprint('0612') or HasFootprint('0805*') or HasFootprint('0815*') or HasFootprint('0830*') or HasFootprint('1206*') or HasFootprint('1210*') or HasFootprint('1808*') or HasFootprint('1812*') or HasFootprint('1825*') or HasFootprint('2010*') or HasFootprint('2220*') or HasFootprint('2225*') or HasFootprint('2512*') or HasFootprint('2728*') or HasFootprint('3518*')] p7: gap=10 collisioncheckmode=3 verticalgap=10 showdistances=TRUE
ComponentClearance ComponentClearance_ViaTP-to-ViaTP [HasFootprint('TP_VIA_*') vs HasFootprint('TP_VIA_*')] p8: gap=1 collisioncheckmode=3 verticalgap=10 showdistances=FALSE
ComponentClearance ComponentClearance_THtoSMT [IsThruComponent   and not InComponentClass('Logo') vs IsSMTComponent   and not InComponentClass('Logo')] p9: gap=30 collisioncheckmode=3 verticalgap=30 showdistances=FALSE
ComponentClearance ComponentClearance_THtoTH [IsThruComponent and not (HasFootprint('Amphenol_U77-A1118-200T','TE_1367073-1','FP-615108137421R_CONN_JACK_16MM4_15MM7-MFG')) vs IsThruComponent and not (HasFootprint('Amphenol_U77-A1118-200T','TE_1367073-1','FP-615108137421R_CONN_JACK_16MM4_15MM7-MFG'))] p10: gap=30 collisioncheckmode=3 verticalgap=30 showdistances=FALSE
ComponentClearance [All AND NOT (InComponentClass('Logo') or HasFootprint('Amphenol_U77-A1118-200T','TE_1367073-1','FP-615108137421R_CONN_JACK_16MM4_15MM7-MFG')) vs All AND NOT (InComponentClass('Logo') or HasFootprint('Amphenol_U77-A1118-200T','TE_1367073-1','FP-615108137421R_CONN_JACK_16MM4_15MM7-MFG'))] p11: gap=10 collisioncheckmode=3 verticalgap=10 showdistances=FALSE
DiffPairsRouting DiffPairsRouting_DIFFPAIR100 [InDifferentialPairClass('Diff_100')] p1: maxlimit=9 minlimit=5 mostfreqgap=8 toplayer_mingap=9 toplayer_prefgap=9 toplayer_minwidth=3.5 toplayer_maxwidth=3.5 toplayer_prefwidth=3.5 midlayer1_mingap=8 midlayer1_maxgap=8 midlayer1_minwidth=4 midlayer1_maxwidth=4 midlayer1_prefwidth=4 midlayer2_maxgap=5 midlayer2_prefgap=5 midlayer2_minwidth=3.4 midlayer2_maxwidth=3.4 midlayer2_prefwidth=3.4 midlayer3_maxgap=5 midlayer3_prefgap=5 midlayer3_minwidth=3.4 midlayer3_maxwidth=3.4 midlayer3_prefwidth=3.4 midlayer4_mingap=8 midlayer4_maxgap=8 midlayer4_minwidth=4 midlayer4_maxwidth=4 midlayer4_prefwidth=4 midlayer5_maxgap=5 midlayer5_prefgap=5 midlayer5_minwidth=1.69 midlayer5_maxwidth=1.69 midlayer5_prefwidth=1.69 midlayer6_maxgap=5 midlayer6_prefgap=5 midlayer6_minwidth=1.69 midlayer6_maxwidth=1.69 midlayer6_prefwidth=1.69 bottomlayer_mingap=9 bottomlayer_prefgap=9 bottomlayer_minwidth=3.5 bottomlayer_maxwidth=3.5 bottomlayer_prefwidth=3.5 impedanceprofiledriven=TRUE impedanceprofileid={02599B78-5EED-409D-9464-26C6130FC348} impedanceprofilevalue=100.000000 maxuncoupledlength=1000
DiffPairsRouting DiffPair_DiffPairsRouting [InDifferentialPairClass('diff_100')] p2: maxlimit=9 minlimit=5 mostfreqgap=8 toplayer_mingap=9 toplayer_prefgap=9 toplayer_minwidth=3.5 toplayer_maxwidth=3.5 toplayer_prefwidth=3.5 midlayer1_mingap=8 midlayer1_maxgap=8 midlayer1_minwidth=4 midlayer1_maxwidth=4 midlayer1_prefwidth=4 midlayer2_maxgap=5 midlayer2_prefgap=5 midlayer2_minwidth=3.4 midlayer2_maxwidth=3.4 midlayer2_prefwidth=3.4 midlayer3_maxgap=5 midlayer3_prefgap=5 midlayer3_minwidth=3.4 midlayer3_maxwidth=3.4 midlayer3_prefwidth=3.4 midlayer4_mingap=8 midlayer4_maxgap=8 midlayer4_minwidth=4 midlayer4_maxwidth=4 midlayer4_prefwidth=4 midlayer5_maxgap=5 midlayer5_prefgap=5 midlayer5_minwidth=1.69 midlayer5_maxwidth=1.69 midlayer5_prefwidth=1.69 midlayer6_maxgap=5 midlayer6_prefgap=5 midlayer6_minwidth=1.69 midlayer6_maxwidth=1.69 midlayer6_prefwidth=1.69 bottomlayer_mingap=9 bottomlayer_prefgap=9 bottomlayer_minwidth=3.5 bottomlayer_maxwidth=3.5 bottomlayer_prefwidth=3.5 impedanceprofiledriven=TRUE impedanceprofileid={02599B78-5EED-409D-9464-26C6130FC348} impedanceprofilevalue=100.000000 maxuncoupledlength=500
DiffPairsRouting DiffPair_DiffPairsRouting_1 [InDifferentialPairClass('diff_100')] p3: maxlimit=10 minlimit=10 mostfreqgap=10 toplayer_minwidth=15 toplayer_maxwidth=15 toplayer_prefwidth=15 midlayer1_minwidth=15 midlayer1_maxwidth=15 midlayer1_prefwidth=15 midlayer2_minwidth=15 midlayer2_maxwidth=15 midlayer2_prefwidth=15 midlayer3_minwidth=15 midlayer3_maxwidth=15 midlayer3_prefwidth=15 midlayer4_minwidth=15 midlayer4_maxwidth=15 midlayer4_prefwidth=15 midlayer5_minwidth=15 midlayer5_maxwidth=15 midlayer5_prefwidth=15 midlayer6_minwidth=15 midlayer6_maxwidth=15 midlayer6_prefwidth=15 bottomlayer_minwidth=15 bottomlayer_maxwidth=15 bottomlayer_prefwidth=15 maxuncoupledlength=500
DiffPairsRouting DiffPairsRouting_CDN [InDifferentialPairClass('CDN')] p4: maxlimit=9 minlimit=5 mostfreqgap=8 toplayer_mingap=9 toplayer_prefgap=9 toplayer_minwidth=3.5 toplayer_maxwidth=3.5 toplayer_prefwidth=3.5 midlayer1_mingap=8 midlayer1_maxgap=8 midlayer1_minwidth=4 midlayer1_maxwidth=4 midlayer1_prefwidth=4 midlayer2_maxgap=5 midlayer2_prefgap=5 midlayer2_minwidth=3.4 midlayer2_maxwidth=3.4 midlayer2_prefwidth=3.4 midlayer3_maxgap=5 midlayer3_prefgap=5 midlayer3_minwidth=3.4 midlayer3_maxwidth=3.4 midlayer3_prefwidth=3.4 midlayer4_mingap=8 midlayer4_maxgap=8 midlayer4_minwidth=4 midlayer4_maxwidth=4 midlayer4_prefwidth=4 midlayer5_maxgap=5 midlayer5_prefgap=5 midlayer5_minwidth=1.69 midlayer5_maxwidth=1.69 midlayer5_prefwidth=1.69 midlayer6_maxgap=5 midlayer6_prefgap=5 midlayer6_minwidth=1.69 midlayer6_maxwidth=1.69 midlayer6_prefwidth=1.69 bottomlayer_mingap=9 bottomlayer_prefgap=9 bottomlayer_minwidth=3.5 bottomlayer_maxwidth=3.5 bottomlayer_prefwidth=3.5 impedanceprofiledriven=TRUE impedanceprofileid={02599B78-5EED-409D-9464-26C6130FC348} impedanceprofilevalue=100.000000 maxuncoupledlength=1000
DiffPairsRouting DiffPairsRouting_DIFFPAIR100POWER [InDifferentialPairClass('Diff_100_power')] p5: maxlimit=10 minlimit=10 mostfreqgap=10 toplayer_minwidth=15 toplayer_maxwidth=25 toplayer_prefwidth=20 midlayer1_minwidth=15 midlayer1_maxwidth=15 midlayer1_prefwidth=15 midlayer2_minwidth=15 midlayer2_maxwidth=15 midlayer2_prefwidth=15 midlayer3_minwidth=15 midlayer3_maxwidth=15 midlayer3_prefwidth=15 midlayer4_minwidth=15 midlayer4_maxwidth=15 midlayer4_prefwidth=15 midlayer5_minwidth=15 midlayer5_maxwidth=15 midlayer5_prefwidth=15 midlayer6_minwidth=15 midlayer6_maxwidth=15 midlayer6_prefwidth=15 bottomlayer_minwidth=15 bottomlayer_maxwidth=25 bottomlayer_prefwidth=20 maxuncoupledlength=500
DiffPairsRouting DiffPairsRouting_USB [InDifferentialPairClass('USB')] p6: maxlimit=5 minlimit=5 mostfreqgap=5 toplayer_minwidth=4 toplayer_maxwidth=4 toplayer_prefwidth=4 midlayer1_minwidth=4 midlayer1_maxwidth=4 midlayer1_prefwidth=4 midlayer2_minwidth=5.09 midlayer2_maxwidth=5.09 midlayer2_prefwidth=5.09 midlayer3_minwidth=5.09 midlayer3_maxwidth=5.09 midlayer3_prefwidth=5.09 midlayer4_minwidth=4 midlayer4_maxwidth=4 midlayer4_prefwidth=4 midlayer5_minwidth=2.37 midlayer5_maxwidth=2.37 midlayer5_prefwidth=2.37 midlayer6_minwidth=2.37 midlayer6_maxwidth=2.37 midlayer6_prefwidth=2.37 bottomlayer_minwidth=4 bottomlayer_maxwidth=4 bottomlayer_prefwidth=4 impedanceprofiledriven=TRUE impedanceprofileid={CD652BC2-D3AC-48A5-BF8E-CEDDD12A97B6} impedanceprofilevalue=90.000000 maxuncoupledlength=500
FabricationTestPointUsage TestPointUsage [All] p1: valid=2 allowmultiple=FALSE
FabricationTestpoint Testpoint [All] p1: side=3 testpointundercomponent=TRUE minsize=40 maxsize=100 preferedsize=60 minholesize=0 maxholesize=40 preferedholesize=32 testpointgrid=1 allowsidetop=TRUE allowsidebottom=TRUE usegrid=TRUE gridtolerance=0.01
FanoutControl Fanout_LCC [IsLCC] p1: bgadir=Out bgaviamode=Centered fanoutstyle=Auto fanoutdirection=Alternating viagrid=1 // Fanout_LCC (Default Rule)
FanoutControl Fanout_BGA [IsBGA] p2: bgadir=Out bgaviamode=Centered fanoutstyle=Auto fanoutdirection=Alternating viagrid=1 // Fanout_BGA (Default Rule)
FanoutControl Fanout_Default [All] p4: bgadir=Out bgaviamode=Centered fanoutstyle=Auto fanoutdirection=Alternating viagrid=1 // Fanout_Default (Default Rule)
FanoutControl Fanout_Small [(CompPinCount < 5)] p5: bgadir=Out bgaviamode=Centered fanoutstyle=Auto fanoutdirection=OutThenIn viagrid=1 // Fanout_Small (Default Rule)
HoleSize [All] p1: absolutevalues=TRUE maxlimit=251 minlimit=7.87 maxpercent=80.000 minpercent=20.000
HoleToHoleClearance [All] p1: gap=7.87 allowstackedmicrovias=FALSE
MatchedLengths MatchedLengths_DiffPairs [InAnyDifferentialPair] p1: tolerance=19.68 checknetsindiffpair=TRUE checkdiffpairvsdiffpair=FALSE checkxsignals=FALSE checkothers=FALSE
MatchedLengths DiffPair_MatchedLengths [InDifferentialPairClass('diff_100')] p2: tolerance=1000 checknetsindiffpair=TRUE checkdiffpairvsdiffpair=FALSE checkxsignals=FALSE checkothers=FALSE
MatchedLengths DiffPair_MatchedLengths_1 [InDifferentialPairClass('diff_100')] p3: tolerance=1000 checknetsindiffpair=FALSE checkdiffpairvsdiffpair=TRUE checkxsignals=TRUE checkothers=TRUE
MatchedLengths MatchLengths_xSignals_PHY1_RX [InxSignalClass('PHY1_RX_LENGTH')] p4: tolerance=10 checknetsindiffpair=FALSE checkdiffpairvsdiffpair=TRUE checkxsignals=TRUE checkothers=TRUE
MatchedLengths MatchLengths_xSignals_PHY1_TX [InxSignalClass('PHY1_TX_LENGTH')] p5: tolerance=10 checknetsindiffpair=FALSE checkdiffpairvsdiffpair=TRUE checkxsignals=TRUE checkothers=TRUE
MatchedLengths MatchLengths_xSignals_PHY2_TX [InxSignalClass('PHY2_TX_LENGTH')] p6: tolerance=10 checknetsindiffpair=FALSE checkdiffpairvsdiffpair=TRUE checkxsignals=TRUE checkothers=TRUE
MatchedLengths MatchLengths_xSignals_PHY2_RX [InxSignalClass('PHY2_RX_LENGTH')] p7: tolerance=10 checknetsindiffpair=FALSE checkdiffpairvsdiffpair=TRUE checkxsignals=TRUE checkothers=TRUE
MatchedLengths MatchLengths_xSignals_PHY3_RX [InxSignalClass('PHY3_RX_LENGTH')] p8: tolerance=10 checknetsindiffpair=FALSE checkdiffpairvsdiffpair=TRUE checkxsignals=TRUE checkothers=TRUE
MatchedLengths MatchLengths_xSignals_PHY3_TX [InxSignalClass('PHY3_TX_LENGTH')] p9: tolerance=10 checknetsindiffpair=FALSE checkdiffpairvsdiffpair=TRUE checkxsignals=TRUE checkothers=TRUE
MatchedLengths MatchLengths_xSignals_PHY4_TX [InxSignalClass('PHY4_TX_LENGTH')] p10: tolerance=10 checknetsindiffpair=FALSE checkdiffpairvsdiffpair=TRUE checkxsignals=TRUE checkothers=TRUE
MatchedLengths MatchLengths_xSignals_PHY5_TX [InxSignalClass('PHY5_TX_LENGTH')] p11: tolerance=15 checknetsindiffpair=FALSE checkdiffpairvsdiffpair=TRUE checkxsignals=TRUE checkothers=TRUE
MatchedLengths MatchLengths_xSignals_PHY5_RX [InxSignalClass('PHY5_RX_LENGTH')] p12: tolerance=15 checknetsindiffpair=FALSE checkdiffpairvsdiffpair=TRUE checkxsignals=TRUE checkothers=TRUE
MatchedLengths MatchLengths_xSignals_PHY4_RX [InxSignalClass('PHY4_RX_LENGTH')] p13: tolerance=10 checknetsindiffpair=FALSE checkdiffpairvsdiffpair=TRUE checkxsignals=TRUE checkothers=TRUE
MatchedLengths MatchLengths_xSignals_RGMII0_TX [InxSignalClass('xSignals_RGMII0_TX_MatchLengthsClass')] p14: tolerance=10 checknetsindiffpair=FALSE checkdiffpairvsdiffpair=TRUE checkxsignals=TRUE checkothers=TRUE
MatchedLengths MatchLengths_xSignals_RGMII0_RX [InxSignalClass('xSignals_RGMII0_RX_MatchLengthsClass')] p15: tolerance=10 checknetsindiffpair=FALSE checkdiffpairvsdiffpair=TRUE checkxsignals=TRUE checkothers=TRUE
MinimumAnnularRing MinimumAnnularRing_ThermalPadVias [IsVia and InAnyComponent] p1: minimumring=5.91
MinimumAnnularRing [All] p2: minimumring=5.91
MinimumSolderMaskSliver MinimumSolderMaskSliver_Logo [InComponentClass('Logo') vs InComponentClass('Logo')] p1: minsoldermaskwidth=0.7
MinimumSolderMaskSliver [All] p2: minsoldermaskwidth=2.72
PlaneConnect [All] p1: planeconnectstyle=Relief reliefexpansion=10 reliefentries=4 reliefconductorwidth=10 reliefairgap=10
PolygonConnect PolygonConnect_49 [All vs IsNamedPolygon('L01_-_TOP_GND_P371')] p1: thpad.connectstyle=Relief thpad.reliefconductorwidth=10 thpad.reliefentries=4 thpad.polygonreliefangle="90 Angle" thpad.airgapwidth=10 smdpad.connectstyle=Direct smdpad.reliefconductorwidth=10 smdpad.reliefentries=4 smdpad.polygonreliefangle="90 Angle" smdpad.airgapwidth=10 via.connectstyle=Direct via.reliefconductorwidth=10 via.reliefentries=4 via.polygonreliefangle="90 Angle" via.airgapwidth=10
PolygonConnect PolygonConnect_48 [All vs IsNamedPolygon('L01_-_TOP_5V_P254')] p2: thpad.connectstyle=Relief thpad.reliefconductorwidth=10 thpad.reliefentries=4 thpad.polygonreliefangle="90 Angle" thpad.airgapwidth=10 smdpad.connectstyle=Direct smdpad.reliefconductorwidth=10 smdpad.reliefentries=4 smdpad.polygonreliefangle="90 Angle" smdpad.airgapwidth=10 via.connectstyle=Direct via.reliefconductorwidth=10 via.reliefentries=4 via.polygonreliefangle="90 Angle" via.airgapwidth=10
PolygonConnect PolygonConnect_47 [All vs IsNamedPolygon('L01_-_TOP_5V_P309')] p3: thpad.connectstyle=Relief thpad.reliefconductorwidth=10 thpad.reliefentries=4 thpad.polygonreliefangle="90 Angle" thpad.airgapwidth=10 smdpad.connectstyle=Direct smdpad.reliefconductorwidth=10 smdpad.reliefentries=4 smdpad.polygonreliefangle="90 Angle" smdpad.airgapwidth=10 via.connectstyle=Direct via.reliefconductorwidth=10 via.reliefentries=4 via.polygonreliefangle="90 Angle" via.airgapwidth=10
PolygonConnect PolygonConnect_46 [All vs IsNamedPolygon('L01_-_TOP_1V8_P310')] p4: thpad.connectstyle=Relief thpad.reliefconductorwidth=10 thpad.reliefentries=4 thpad.polygonreliefangle="90 Angle" thpad.airgapwidth=10 smdpad.connectstyle=Direct smdpad.reliefconductorwidth=10 smdpad.reliefentries=4 smdpad.polygonreliefangle="90 Angle" smdpad.airgapwidth=10 via.connectstyle=Direct via.reliefconductorwidth=10 via.reliefentries=4 via.polygonreliefangle="90 Angle" via.airgapwidth=10
PolygonConnect PolygonConnect_45 [All vs IsNamedPolygon('L07_-_GND_GND_P358')] p5: thpad.connectstyle=Relief thpad.reliefconductorwidth=10 thpad.reliefentries=4 thpad.polygonreliefangle="90 Angle" thpad.airgapwidth=10 smdpad.connectstyle=Direct smdpad.reliefconductorwidth=10 smdpad.reliefentries=4 smdpad.polygonreliefangle="90 Angle" smdpad.airgapwidth=10 via.connectstyle=Direct via.reliefconductorwidth=10 via.reliefentries=4 via.polygonreliefangle="90 Angle" via.airgapwidth=10
PolygonConnect PolygonConnect_44 [All vs IsNamedPolygon('L02_-_GND_GND_P332')] p6: thpad.connectstyle=Relief thpad.reliefconductorwidth=10 thpad.reliefentries=4 thpad.polygonreliefangle="90 Angle" thpad.airgapwidth=10 smdpad.connectstyle=Direct smdpad.reliefconductorwidth=10 smdpad.reliefentries=4 smdpad.polygonreliefangle="90 Angle" smdpad.airgapwidth=10 via.connectstyle=Direct via.reliefconductorwidth=10 via.reliefentries=4 via.polygonreliefangle="90 Angle" via.airgapwidth=10
PolygonConnect PolygonConnect_43 [All vs IsNamedPolygon('L04_-_GND_GND_P372')] p7: thpad.connectstyle=Relief thpad.reliefconductorwidth=10 thpad.reliefentries=4 thpad.polygonreliefangle="90 Angle" thpad.airgapwidth=10 smdpad.connectstyle=Direct smdpad.reliefconductorwidth=10 smdpad.reliefentries=4 smdpad.polygonreliefangle="90 Angle" smdpad.airgapwidth=10 via.connectstyle=Direct via.reliefconductorwidth=10 via.reliefentries=4 via.polygonreliefangle="90 Angle" via.airgapwidth=10
PolygonConnect PolygonConnect_42 [All vs IsNamedPolygon('L08_-_BOTTOM_GND_P374')] p8: thpad.connectstyle=Relief thpad.reliefconductorwidth=10 thpad.reliefentries=4 thpad.polygonreliefangle="90 Angle" thpad.airgapwidth=10 smdpad.connectstyle=Direct smdpad.reliefconductorwidth=10 smdpad.reliefentries=4 smdpad.polygonreliefangle="90 Angle" smdpad.airgapwidth=10 via.connectstyle=Direct via.reliefconductorwidth=10 via.reliefentries=4 via.polygonreliefangle="90 Angle" via.airgapwidth=10
PolygonConnect PolygonConnect_41 [All vs IsNamedPolygon('L01_-_TOP_GND_P366')] p9: thpad.connectstyle=Relief thpad.reliefconductorwidth=10 thpad.reliefentries=4 thpad.polygonreliefangle="90 Angle" thpad.airgapwidth=10 smdpad.connectstyle=Direct smdpad.reliefconductorwidth=10 smdpad.reliefentries=4 smdpad.polygonreliefangle="90 Angle" smdpad.airgapwidth=10 via.connectstyle=Direct via.reliefconductorwidth=10 via.reliefentries=4 via.polygonreliefangle="90 Angle" via.airgapwidth=10
PolygonConnect PolygonConnect_40 [All vs IsNamedPolygon('L01_-_TOP_GND_P366')] p10: thpad.connectstyle=Relief thpad.reliefconductorwidth=10 thpad.reliefentries=4 thpad.polygonreliefangle="90 Angle" thpad.airgapwidth=10 smdpad.connectstyle=Direct smdpad.reliefconductorwidth=10 smdpad.reliefentries=4 smdpad.polygonreliefangle="90 Angle" smdpad.airgapwidth=10 via.connectstyle=Direct via.reliefconductorwidth=10 via.reliefentries=4 via.polygonreliefangle="90 Angle" via.airgapwidth=10
PolygonConnect PolygonConnect_39 [All vs IsNamedPolygon('L01_-_TOP_24V_P308')] p11: thpad.connectstyle=Relief thpad.reliefconductorwidth=10 thpad.reliefentries=4 thpad.polygonreliefangle="90 Angle" thpad.airgapwidth=10 smdpad.connectstyle=Direct smdpad.reliefconductorwidth=10 smdpad.reliefentries=4 smdpad.polygonreliefangle="90 Angle" smdpad.airgapwidth=10 via.connectstyle=Direct via.reliefconductorwidth=10 via.reliefentries=4 via.polygonreliefangle="90 Angle" via.airgapwidth=10
PolygonConnect PolygonConnect_38 [All vs IsNamedPolygon('L01_-_TOP_GND_P315')] p12: thpad.connectstyle=Relief thpad.reliefconductorwidth=10 thpad.reliefentries=4 thpad.polygonreliefangle="90 Angle" thpad.airgapwidth=10 smdpad.connectstyle=Direct smdpad.reliefconductorwidth=10 smdpad.reliefentries=4 smdpad.polygonreliefangle="90 Angle" smdpad.airgapwidth=10 via.connectstyle=Direct via.reliefconductorwidth=10 via.reliefentries=4 via.polygonreliefangle="90 Angle" via.airgapwidth=10
PolygonConnect PolygonConnect_37 [All vs IsNamedPolygon('L01_-_TOP_5V_P314')] p13: thpad.connectstyle=Relief thpad.reliefconductorwidth=10 thpad.reliefentries=4 thpad.polygonreliefangle="90 Angle" thpad.airgapwidth=10 smdpad.connectstyle=Direct smdpad.reliefconductorwidth=10 smdpad.reliefentries=4 smdpad.polygonreliefangle="90 Angle" smdpad.airgapwidth=10 via.connectstyle=Direct via.reliefconductorwidth=10 via.reliefentries=4 via.polygonreliefangle="90 Angle" via.airgapwidth=10
PolygonConnect PolygonConnect_36 [All vs IsNamedPolygon('L01_-_TOP_5V_P254')] p14: connectstyle=Direct reliefconductorwidth=10 reliefentries=4 polygonreliefangle="90 Angle" airgapwidth=10
PolygonConnect PolygonConnect_35 [All vs IsNamedPolygon('L01_-_TOP_5V_P364')] p15: thpad.connectstyle=Relief thpad.reliefconductorwidth=10 thpad.reliefentries=4 thpad.polygonreliefangle="90 Angle" thpad.airgapwidth=10 smdpad.connectstyle=Direct smdpad.reliefconductorwidth=10 smdpad.reliefentries=4 smdpad.polygonreliefangle="90 Angle" smdpad.airgapwidth=10 via.connectstyle=Direct via.reliefconductorwidth=10 via.reliefentries=4 via.polygonreliefangle="90 Angle" via.airgapwidth=10
PolygonConnect PolygonConnect_34 [All vs IsNamedPolygon('L01_-_TOP_1V8_P362')] p16: thpad.connectstyle=Relief thpad.reliefconductorwidth=10 thpad.reliefentries=4 thpad.polygonreliefangle="90 Angle" thpad.airgapwidth=10 smdpad.connectstyle=Direct smdpad.reliefconductorwidth=10 smdpad.reliefentries=4 smdpad.polygonreliefangle="90 Angle" smdpad.airgapwidth=10 via.connectstyle=Direct via.reliefconductorwidth=10 via.reliefentries=4 via.polygonreliefangle="90 Angle" via.airgapwidth=10
PolygonConnect PolygonConnect_33 [All vs IsNamedPolygon('L01_-_TOP_GND_P366')] p17: thpad.connectstyle=Relief thpad.reliefconductorwidth=10 thpad.reliefentries=4 thpad.polygonreliefangle="90 Angle" thpad.airgapwidth=10 smdpad.connectstyle=Direct smdpad.reliefconductorwidth=10 smdpad.reliefentries=4 smdpad.polygonreliefangle="90 Angle" smdpad.airgapwidth=10 via.connectstyle=Direct via.reliefconductorwidth=10 via.reliefentries=4 via.polygonreliefangle="90 Angle" via.airgapwidth=10
PolygonConnect PolygonConnect_32 [All vs IsNamedPolygon('L01_-_TOP_24V_P308')] p18: thpad.connectstyle=Relief thpad.reliefconductorwidth=10 thpad.reliefentries=4 thpad.polygonreliefangle="90 Angle" thpad.airgapwidth=10 smdpad.connectstyle=Direct smdpad.reliefconductorwidth=10 smdpad.reliefentries=4 smdpad.polygonreliefangle="90 Angle" smdpad.airgapwidth=10 via.connectstyle=Direct via.reliefconductorwidth=10 via.reliefentries=4 via.polygonreliefangle="90 Angle" via.airgapwidth=10
PolygonConnect PolygonConnect_31 [All vs IsNamedPolygon('L01_-_TOP_24V_P167')] p19: thpad.connectstyle=Relief thpad.reliefconductorwidth=10 thpad.reliefentries=4 thpad.polygonreliefangle="90 Angle" thpad.airgapwidth=10 smdpad.connectstyle=Direct smdpad.reliefconductorwidth=10 smdpad.reliefentries=4 smdpad.polygonreliefangle="90 Angle" smdpad.airgapwidth=10 via.connectstyle=Direct via.reliefconductorwidth=10 via.reliefentries=4 via.polygonreliefangle="90 Angle" via.airgapwidth=10
PolygonConnect PolygonConnect_30 [All vs IsNamedPolygon('L01_-_TOP_24V_P166')] p20: thpad.connectstyle=Relief thpad.reliefconductorwidth=10 thpad.reliefentries=4 thpad.polygonreliefangle="90 Angle" thpad.airgapwidth=10 smdpad.connectstyle=Direct smdpad.reliefconductorwidth=10 smdpad.reliefentries=4 smdpad.polygonreliefangle="90 Angle" smdpad.airgapwidth=10 via.connectstyle=Direct via.reliefconductorwidth=10 via.reliefentries=4 via.polygonreliefangle="90 Angle" via.airgapwidth=10
PolygonConnect PolygonConnect_29 [All vs IsNamedPolygon('L05 - PWR-5V')] p21: connectstyle=Direct reliefconductorwidth=10 reliefentries=4 polygonreliefangle="90 Angle" airgapwidth=10
PolygonConnect PolygonConnect_28 [All vs IsNamedPolygon('L01_-_TOP_GND_P173')] p22: thpad.connectstyle=Relief thpad.reliefconductorwidth=10 thpad.reliefentries=4 thpad.polygonreliefangle="90 Angle" thpad.airgapwidth=10 smdpad.connectstyle=Direct smdpad.reliefconductorwidth=10 smdpad.reliefentries=4 smdpad.polygonreliefangle="90 Angle" smdpad.airgapwidth=10 via.connectstyle=Direct via.reliefconductorwidth=10 via.reliefentries=4 via.polygonreliefangle="90 Angle" via.airgapwidth=10
PolygonConnect PolygonConnect_27 [All vs IsNamedPolygon('L01_-_TOP_5V_P172')] p23: thpad.connectstyle=Relief thpad.reliefconductorwidth=10 thpad.reliefentries=4 thpad.polygonreliefangle="90 Angle" thpad.airgapwidth=10 smdpad.connectstyle=Direct smdpad.reliefconductorwidth=10 smdpad.reliefentries=4 smdpad.polygonreliefangle="90 Angle" smdpad.airgapwidth=10 via.connectstyle=Direct via.reliefconductorwidth=10 via.reliefentries=4 via.polygonreliefangle="90 Angle" via.airgapwidth=10
PolygonConnect PolygonConnect_26 [All vs IsNamedPolygon('L01_-_TOP_GND_P207')] p24: thpad.connectstyle=Relief thpad.reliefconductorwidth=10 thpad.reliefentries=4 thpad.polygonreliefangle="90 Angle" thpad.airgapwidth=10 smdpad.connectstyle=Direct smdpad.reliefconductorwidth=10 smdpad.reliefentries=4 smdpad.polygonreliefangle="90 Angle" smdpad.airgapwidth=10 via.connectstyle=Direct via.reliefconductorwidth=10 via.reliefentries=4 via.polygonreliefangle="90 Angle" via.airgapwidth=10
PolygonConnect PolygonConnect_25 [All vs IsNamedPolygon('L01_-_TOP_NETC113_1_P206')] p25: thpad.connectstyle=Relief thpad.reliefconductorwidth=10 thpad.reliefentries=4 thpad.polygonreliefangle="90 Angle" thpad.airgapwidth=10 smdpad.connectstyle=Direct smdpad.reliefconductorwidth=10 smdpad.reliefentries=4 smdpad.polygonreliefangle="90 Angle" smdpad.airgapwidth=10 via.connectstyle=Relief via.reliefconductorwidth=10 via.reliefentries=4 via.polygonreliefangle="90 Angle" via.airgapwidth=10
PolygonConnect PolygonConnect_24 [All vs IsNamedPolygon('L01_-_TOP_6.5V_P165')] p26: thpad.connectstyle=Relief thpad.reliefconductorwidth=10 thpad.reliefentries=4 thpad.polygonreliefangle="90 Angle" thpad.airgapwidth=10 smdpad.connectstyle=Direct smdpad.reliefconductorwidth=10 smdpad.reliefentries=4 smdpad.polygonreliefangle="90 Angle" smdpad.airgapwidth=10 via.connectstyle=Direct via.reliefconductorwidth=10 via.reliefentries=4 via.polygonreliefangle="90 Angle" via.airgapwidth=10
PolygonConnect PolygonConnect_23 [All vs IsNamedPolygon('L01_-_TOP_NETC139_1_P185')] p27: thpad.connectstyle=Relief thpad.reliefconductorwidth=10 thpad.reliefentries=4 thpad.polygonreliefangle="90 Angle" thpad.airgapwidth=10 smdpad.connectstyle=Direct smdpad.reliefconductorwidth=10 smdpad.reliefentries=4 smdpad.polygonreliefangle="90 Angle" smdpad.airgapwidth=10 via.connectstyle=Direct via.reliefconductorwidth=10 via.reliefentries=4 via.polygonreliefangle="90 Angle" via.airgapwidth=10
PolygonConnect PolygonConnect_22 [All vs IsNamedPolygon('L01_-_TOP_3V3_P174')] p28: thpad.connectstyle=Relief thpad.reliefconductorwidth=10 thpad.reliefentries=4 thpad.polygonreliefangle="90 Angle" thpad.airgapwidth=10 smdpad.connectstyle=Direct smdpad.reliefconductorwidth=10 smdpad.reliefentries=4 smdpad.polygonreliefangle="90 Angle" smdpad.airgapwidth=10 via.connectstyle=Direct via.reliefconductorwidth=10 via.reliefentries=4 via.polygonreliefangle="90 Angle" via.airgapwidth=10
PolygonConnect PolygonConnect_21 [All vs IsNamedPolygon('L01_-_TOP_GND_P169')] p29: thpad.connectstyle=Relief thpad.reliefconductorwidth=10 thpad.reliefentries=4 thpad.polygonreliefangle="90 Angle" thpad.airgapwidth=10 smdpad.connectstyle=Direct smdpad.reliefconductorwidth=10 smdpad.reliefentries=4 smdpad.polygonreliefangle="90 Angle" smdpad.airgapwidth=10 via.connectstyle=Direct via.reliefconductorwidth=10 via.reliefentries=4 via.polygonreliefangle="90 Angle" via.airgapwidth=10
PolygonConnect PolygonConnect_20 [All vs IsNamedPolygon('L01_-_TOP_5V_P171')] p30: thpad.connectstyle=Relief thpad.reliefconductorwidth=10 thpad.reliefentries=4 thpad.polygonreliefangle="90 Angle" thpad.airgapwidth=10 smdpad.connectstyle=Direct smdpad.reliefconductorwidth=10 smdpad.reliefentries=4 smdpad.polygonreliefangle="90 Angle" smdpad.airgapwidth=10 via.connectstyle=Direct via.reliefconductorwidth=10 via.reliefentries=4 via.polygonreliefangle="90 Angle" via.airgapwidth=10
PolygonConnect PolygonConnect_19 [All vs IsNamedPolygon('L01_-_TOP_1V8_P170')] p31: thpad.connectstyle=Relief thpad.reliefconductorwidth=10 thpad.reliefentries=4 thpad.polygonreliefangle="90 Angle" thpad.airgapwidth=10 smdpad.connectstyle=Direct smdpad.reliefconductorwidth=10 smdpad.reliefentries=4 smdpad.polygonreliefangle="90 Angle" smdpad.airgapwidth=10 via.connectstyle=Direct via.reliefconductorwidth=10 via.reliefentries=4 via.polygonreliefangle="90 Angle" via.airgapwidth=10
PolygonConnect PolygonConnect_18 [All vs IsNamedPolygon('L01_-_TOP_NONET_P081')] p32: connectstyle=Direct reliefconductorwidth=10 reliefentries=4 polygonreliefangle="90 Angle" airgapwidth=10
PolygonConnect PolygonConnect_17 [All vs IsNamedPolygon('L01_-_TOP_NONET_P080')] p33: connectstyle=Direct reliefconductorwidth=10 reliefentries=4 polygonreliefangle="90 Angle" airgapwidth=10
PolygonConnect PolygonConnect_16 [All vs IsNamedPolygon('L01_-_TOP_NONET_P074')] p34: connectstyle=Direct reliefconductorwidth=10 reliefentries=4 polygonreliefangle="90 Angle" airgapwidth=10
PolygonConnect PolygonConnect_15 [All vs IsNamedPolygon('L01_-_TOP_NONET_P091')] p35: connectstyle=Direct reliefconductorwidth=10 reliefentries=4 polygonreliefangle="90 Angle" airgapwidth=10
PolygonConnect PolygonConnect_14 [All vs IsNamedPolygon('L01_-_TOP_NONET_P090')] p36: thpad.connectstyle=Relief thpad.reliefconductorwidth=10 thpad.reliefentries=4 thpad.polygonreliefangle="90 Angle" thpad.airgapwidth=10 smdpad.connectstyle=Direct smdpad.reliefconductorwidth=10 smdpad.reliefentries=4 smdpad.polygonreliefangle="90 Angle" smdpad.airgapwidth=10 via.connectstyle=Direct via.reliefconductorwidth=10 via.reliefentries=4 via.polygonreliefangle="90 Angle" via.airgapwidth=10
PolygonConnect PolygonConnect_13 [All vs IsNamedPolygon('L01_-_TOP_NONET_P089')] p37: thpad.connectstyle=Relief thpad.reliefconductorwidth=10 thpad.reliefentries=4 thpad.polygonreliefangle="90 Angle" thpad.airgapwidth=10 smdpad.connectstyle=Direct smdpad.reliefconductorwidth=10 smdpad.reliefentries=4 smdpad.polygonreliefangle="90 Angle" smdpad.airgapwidth=10 via.connectstyle=Direct via.reliefconductorwidth=10 via.reliefentries=4 via.polygonreliefangle="90 Angle" via.airgapwidth=10
PolygonConnect PolygonConnect_12 [All vs IsNamedPolygon('L01_-_TOP_NONET_P088')] p38: thpad.connectstyle=Relief thpad.reliefconductorwidth=10 thpad.reliefentries=4 thpad.polygonreliefangle="90 Angle" thpad.airgapwidth=10 smdpad.connectstyle=Direct smdpad.reliefconductorwidth=10 smdpad.reliefentries=4 smdpad.polygonreliefangle="90 Angle" smdpad.airgapwidth=10 via.connectstyle=Direct via.reliefconductorwidth=10 via.reliefentries=4 via.polygonreliefangle="90 Angle" via.airgapwidth=10
PolygonConnect PolygonConnect_11 [All vs IsNamedPolygon('L01_-_TOP_NONET_P087')] p39: connectstyle=Direct reliefconductorwidth=10 reliefentries=4 polygonreliefangle="90 Angle" airgapwidth=10
PolygonConnect PolygonConnect_10 [All vs IsNamedPolygon('L01_-_TOP_NONET_P086')] p40: thpad.connectstyle=Relief thpad.reliefconductorwidth=10 thpad.reliefentries=4 thpad.polygonreliefangle="90 Angle" thpad.airgapwidth=10 smdpad.connectstyle=Direct smdpad.reliefconductorwidth=10 smdpad.reliefentries=4 smdpad.polygonreliefangle="90 Angle" smdpad.airgapwidth=10 via.connectstyle=Direct via.reliefconductorwidth=10 via.reliefentries=4 via.polygonreliefangle="90 Angle" via.airgapwidth=10
PolygonConnect PolygonConnect_9 [All vs IsNamedPolygon('L01_-_TOP_NONET_P085')] p41: thpad.connectstyle=Relief thpad.reliefconductorwidth=10 thpad.reliefentries=4 thpad.polygonreliefangle="90 Angle" thpad.airgapwidth=10 smdpad.connectstyle=Direct smdpad.reliefconductorwidth=10 smdpad.reliefentries=4 smdpad.polygonreliefangle="90 Angle" smdpad.airgapwidth=10 via.connectstyle=Direct via.reliefconductorwidth=10 via.reliefentries=4 via.polygonreliefangle="90 Angle" via.airgapwidth=10
PolygonConnect PolygonConnect_8 [All vs IsNamedPolygon('L01_-_TOP_NONET_P079')] p42: thpad.connectstyle=Relief thpad.reliefconductorwidth=10 thpad.reliefentries=4 thpad.polygonreliefangle="90 Angle" thpad.airgapwidth=10 smdpad.connectstyle=Direct smdpad.reliefconductorwidth=10 smdpad.reliefentries=4 smdpad.polygonreliefangle="90 Angle" smdpad.airgapwidth=10 via.connectstyle=Direct via.reliefconductorwidth=10 via.reliefentries=4 via.polygonreliefangle="90 Angle" via.airgapwidth=10
PolygonConnect PolygonConnect_7 [All vs IsNamedPolygon('L01_-_TOP_NONET_P080')] p43: thpad.connectstyle=Relief thpad.reliefconductorwidth=10 thpad.reliefentries=4 thpad.polygonreliefangle="90 Angle" thpad.airgapwidth=10 smdpad.connectstyle=Direct smdpad.reliefconductorwidth=10 smdpad.reliefentries=4 smdpad.polygonreliefangle="90 Angle" smdpad.airgapwidth=10 via.connectstyle=Direct via.reliefconductorwidth=10 via.reliefentries=4 via.polygonreliefangle="90 Angle" via.airgapwidth=10
PolygonConnect PolygonConnect_6 [All vs IsNamedPolygon('L01_-_TOP_NONET_P081')] p44: thpad.connectstyle=Relief thpad.reliefconductorwidth=10 thpad.reliefentries=4 thpad.polygonreliefangle="90 Angle" thpad.airgapwidth=10 smdpad.connectstyle=Direct smdpad.reliefconductorwidth=10 smdpad.reliefentries=4 smdpad.polygonreliefangle="90 Angle" smdpad.airgapwidth=10 via.connectstyle=Direct via.reliefconductorwidth=10 via.reliefentries=4 via.polygonreliefangle="90 Angle" via.airgapwidth=10
PolygonConnect PolygonConnect_5 [All vs IsNamedPolygon('L01_-_TOP_5V_P014')] p45: thpad.connectstyle=Relief thpad.reliefconductorwidth=10 thpad.reliefentries=4 thpad.polygonreliefangle="90 Angle" thpad.airgapwidth=10 smdpad.connectstyle=Direct smdpad.reliefconductorwidth=10 smdpad.reliefentries=4 smdpad.polygonreliefangle="90 Angle" smdpad.airgapwidth=10 via.connectstyle=Direct via.reliefconductorwidth=10 via.reliefentries=4 via.polygonreliefangle="90 Angle" via.airgapwidth=10
PolygonConnect PolygonConnect_4 [All vs IsNamedPolygon('L01_-_TOP_5V_P079')] p46: thpad.connectstyle=Relief thpad.reliefconductorwidth=10 thpad.reliefentries=4 thpad.polygonreliefangle="90 Angle" thpad.airgapwidth=10 smdpad.connectstyle=Direct smdpad.reliefconductorwidth=10 smdpad.reliefentries=4 smdpad.polygonreliefangle="90 Angle" smdpad.airgapwidth=10 via.connectstyle=Direct via.reliefconductorwidth=10 via.reliefentries=4 via.polygonreliefangle="90 Angle" via.airgapwidth=10
PolygonConnect PolygonConnect_3 [All vs IsNamedPolygon('L01_-_TOP_NONET_P077')] p47: connectstyle=Direct reliefconductorwidth=10 reliefentries=4 polygonreliefangle="90 Angle" airgapwidth=10
PolygonConnect PolygonConnect_2 [All vs IsNamedPolygon('L01_-_TOP_NONET_P077')] p48: connectstyle=Direct reliefconductorwidth=10 reliefentries=4 polygonreliefangle="90 Angle" airgapwidth=10
PolygonConnect PolygonConnect_1 [All vs IsNamedPolygon('L01_-_TOP_24V_P073')] p49: connectstyle=Direct reliefconductorwidth=10 reliefentries=4 polygonreliefangle="90 Angle" airgapwidth=10
PolygonConnect PolygonConnect_SMD [HasFootprint('0201*') or HasFootprint('0402*') or HasFootprint('0508') or HasFootprint('0603*') or HasFootprint('0612') or HasFootprint('0805*') or HasFootprint('0815*') or HasFootprint('0830*') or HasFootprint('1206*') or HasFootprint('1210*') or HasFootprint('1808*') or HasFootprint('1812*') or HasFootprint('1825*') or HasFootprint('2010*') or HasFootprint('2220*') or HasFootprint('2225*') or HasFootprint('2512*') or HasFootprint('2728*') or HasFootprint('3518*') or IsVia or HasFootprint('SMC*') or HasFootprint('SMA') or HasFootprint('RHF*') or HasFootprint('DQK*') or HasFootprint('DSG*') or HasFootprint('SOT-223') or InComponent('C99') or InComponent('C98') or InComponent('L13') or InComponent('U31') or InComponent('F1') or InComponent('C49') or InComponent('C96') or InComponent('L8') or InComponent('L6')] p50: connectstyle=Direct reliefconductorwidth=10 reliefentries=4 polygonreliefangle="90 Angle" airgapwidth=10
PolygonConnect Polygon_DirectConnect [InPolygonClass('DirectConnect')] p51: connectstyle=Direct reliefconductorwidth=10 reliefentries=4 polygonreliefangle="90 Angle" airgapwidth=10
PolygonConnect [All] p52: connectstyle=Direct reliefconductorwidth=10 reliefentries=4 polygonreliefangle="90 Angle" airgapwidth=10
RoutingLayers [All] p1: top layer_v5=TRUE mid layer 1_v5=TRUE mid layer 2_v5=TRUE mid layer 3_v5=TRUE mid layer 4_v5=TRUE mid layer 5_v5=FALSE mid layer 6_v5=FALSE bottom layer_v5=TRUE
RoutingVias ThermalPadVias [IsVia and InAnyComponent] p1: holewidth=7.87 width=19.68 viastyle="Through Hole" minholewidth=7.87 minwidth=19.68 maxholewidth=12.99 maxwidth=23.62
RoutingVias [All] p2: holewidth=7.87 width=19.68 viastyle="Through Hole" minholewidth=7.87 minwidth=17.72 maxholewidth=27.56 maxwidth=35.43 useviatemplates=TRUE viatemplateguid#1={04F3395F-977C-4E8E-A3F4-120E4D43E6F7} viatemplateguid#2={0A5FD806-0C14-4C02-90BD-80FC126DA0B9} viatemplateguid#3={F1469422-2891-4445-96EC-95961DC5AB1B} viatemplateguid#4={8291C09E-7792-4DA4-A1C6-5E8E83732DAD} viatemplateguid#5={F22AA792-B869-4DFB-AA27-9FA8D231E9CE} viatemplatename#1=v50h20 viatemplatename#2=v50h20m50 viatemplatename#3=v51h20m0mx0 viatemplatename#4=v51h20m0mx0(1) viatemplatename#5=v508h366(Tol8-8)
SilkToBoardRegionClearance [Not ((IsComment or IsDesignator) And (Hide <> 'False')) and not InRegion(1000,500,4000,800)] p1:
SilkToSilkClearance SilkToSilkClearance_Pb-FreeLogo [(HasFootprint('Pb-Free_Overlay_Medium') OR HasFootprint('Pb-Free_Overlay_Small')) vs (HasFootprint('Pb-Free_Overlay_Medium') OR HasFootprint('Pb-Free_Overlay_Small'))] p1: silktosilkclearance=0
SilkToSilkClearance [All] p2: silktosilkclearance=4.33
SilkToSolderMaskClearance SilkToComponentPadClearance [((IsPad or IsFill or IsRegion) and InAnycomponent)  and not isvia vs All       and not IsVia] p1: minsilkscreentomaskgap=3 clearancetoexposedcopper=FALSE
SilkToSolderMaskClearance "Silk to Solder Mask Opening" [All  and not IsVia vs All  and not IsVia] p2 off: minsilkscreentomaskgap=4.92 clearancetoexposedcopper=TRUE
SolderMaskExpansion [All   and not isvia] p1: expansion=1.97 istentingtop=FALSE
SolderMaskExpansion SolderMaskExpansion_Vias [IsVia] p2: expansion=0.98 istentingtop=FALSE soldermaskfromhole=TRUE
SupplyNets "Schematic Supply Nets_22" [InNet('3V3_USB_ISO')] p1: voltage=0.000
SupplyNets "Schematic Supply Nets_21" [InNet('GND_USB')] p2: voltage=0.000
SupplyNets "Schematic Supply Nets_20" [InNet('3V3_USB_FTDI')] p3: voltage=0.000
SupplyNets "Schematic Supply Nets_19" [InNet('24V')] p4: voltage=0.000
SupplyNets "Schematic Supply Nets_18" [InNet('V_VDDSHV5_SD')] p5: voltage=0.000
SupplyNets "Schematic Supply Nets_17" [InNet('VCC_ETH2')] p6: voltage=0.000
SupplyNets "Schematic Supply Nets_16" [InNet('1V1_ETH2')] p7: voltage=0.000
SupplyNets "Schematic Supply Nets_15" [InNet('2V5_ETH1')] p8: voltage=0.000
SupplyNets "Schematic Supply Nets_14" [InNet('1V8')] p9: voltage=0.000
SupplyNets "Schematic Supply Nets_13" [InNet('1V1')] p10: voltage=0.000
SupplyNets "Schematic Supply Nets_12" [InNet('5V')] p11: voltage=0.000
SupplyNets "Schematic Supply Nets_11" [InNet('EARTH_GND')] p12: voltage=0.000
SupplyNets "Schematic Supply Nets_10" [InNet('VCC_ETH1')] p13: voltage=0.000
SupplyNets "Schematic Supply Nets_9" [InNet('2V5')] p14: voltage=0.000
SupplyNets "Schematic Supply Nets_8" [InNet('1V1_ETH1')] p15: voltage=0.000
SupplyNets "Schematic Supply Nets_7" [InNet('3V3_SD')] p16: voltage=0.000
SupplyNets "Schematic Supply Nets_6" [InNet('5V_USB')] p17: voltage=0.000
SupplyNets "Schematic Supply Nets_5" [InNet('VBUS')] p18: voltage=0.000
SupplyNets "Schematic Supply Nets_4" [InNet('3V3')] p19: voltage=0.000
SupplyNets "Schematic Supply Nets_3" [InNet('V_1V8_MOD')] p20: voltage=0.000
SupplyNets "Schematic Supply Nets_2" [InNet('AGND')] p21: voltage=0.000
SupplyNets "Schematic Supply Nets_1" [InNet('GND')] p22: voltage=0.000
SupplyNets "Schematic Supply Nets" [InNet('2V5_ETH2')] p23: voltage=0.000
UnRoutedNet [All] p1: checkbadconnections=TRUE
Width Width_SE50 [InNetClass('SE50')] p1: maxlimit=9.44 minlimit=2.3 preferedwidth=9.44 toplayer_minwidth=4.25 toplayer_maxwidth=4.25 toplayer_prefwidth=4.25 midlayer1_minwidth=5.25 midlayer1_maxwidth=5.25 midlayer1_prefwidth=5.25 midlayer2_minwidth=9.44 midlayer3_minwidth=9.44 midlayer4_minwidth=5.25 midlayer4_maxwidth=5.25 midlayer4_prefwidth=5.25 midlayer5_maxwidth=2.3 midlayer5_prefwidth=2.3 midlayer6_maxwidth=2.3 midlayer6_prefwidth=2.3 bottomlayer_minwidth=4.25 bottomlayer_maxwidth=4.25 bottomlayer_prefwidth=4.25 impedanceprofiledriven=TRUE impedanceprofileid={03E46DD6-267E-40F3-A0D4-71E3C5C909BC} impedanceprofilevalue=50.000000 minimp=50.000000 maximp=50.000000 favimp=50.000000
Width [All] p2: maxlimit=50 minlimit=4.25 preferedwidth=8 toplayer_prefwidth=4.25 midlayer1_minwidth=5.25 midlayer4_minwidth=5.25 bottomlayer_prefwidth=4.25 minimp=50.000000 maximp=50.000000 favimp=50.000000 checkconnectedcopper=TRUE
12 further rules are at their usual default settings.

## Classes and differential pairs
net class SDMCLKx: SDM_CLK_AX12 SDM_CLK_AX34 SDM_CLK_AX56
net class SDCLK: PRU0_SD0_CLK_SHIFT PRU0_SD3_CLK_SHIFT PRU1_SD0_CLK_SHIFT PRU1_SD3_CLK_SHIFT
net class DOUT_3V3: DOUT_A1_SDM DOUT_A2_SDM DOUT_A3_SDM DOUT_A4_SDM DOUT_A5_SDM DOUT_A6_SDM DOUT_B1_SDM DOUT_B2_SDM DOUT_B3_SDM DOUT_B4_SDM DOUT_B5_SDM DOUT_B6_SDM
net class DOUT_1V8: DOUT_A1 DOUT_A2 DOUT_A3 DOUT_A4 DOUT_A5 DOUT_A6 DOUT_B1 DOUT_B2 DOUT_B3 DOUT_B4 DOUT_B5 DOUT_B6
net class ETH2_RX: ETH2_RGMII2_RD0 ETH2_RGMII2_RD1 ETH2_RGMII2_RD2 ETH2_RGMII2_RD3 ETH2_RGMII2_RX_ER ETH2_RGMII2_RXC
net class ETH2_TX: ETH2_RGMII2_TD0 ETH2_RGMII2_TD1 ETH2_RGMII2_TD2 ETH2_RGMII2_TD3 ETH2_RGMII2_TXC
net class ETH1_RX: ETH1_RGMII1_RD0 ETH1_RGMII1_RD1 ETH1_RGMII1_RD2 ETH1_RGMII1_RD3 ETH1_RGMII1_RX_ER ETH1_RGMII1_RXC
net class ETH1_TX: ETH1_RGMII1_TD0 ETH1_RGMII1_TD1 ETH1_RGMII1_TD2 ETH1_RGMII1_TD3 ETH1_RGMII1_TXC
differential pair class diff_100: E1_TD_A E1_TD_B E1_TD_C E1_TD_D E2_TD_A E2_TD_B E2_TD_C E2_TD_D ETH1_TD_A ETH1_TD_B ETH1_TD_C ETH1_TD_D ETH2_TD_A ETH2_TD_B ETH2_TD_C ETH2_TD_D
net class MMC1: MMC1_CLK MMC1_CMD MMC1_DAT0 MMC1_DAT1 MMC1_DAT2 MMC1_DAT3
differential pair class USB: FTDI_USB_D
component class TIDA-010948-CB-SDFM: C47 C48 C49 C50 C51 C52 R95 R96 R97 R98 R99 R100 R101 R102 R103 R104 R105 R106 R241 R268 R276 R281 R291 R317 U18 U19 U20
component class TIDA-010948-CB-PWM: 22 C67 C68 C69 C70 C71 C72 C73 C74 C75 C76 C77 C78 C79 C80 C81 C82 C83 C84 C85 C86 C87 C88 C89 C90 C91 C92 C93 C94 C95 C96 C97 C98 C99 C100 C101 C102 C103 C104 C105 C106 C107 C108 C112 C120 C126 C132 C154 C162 R129 R130 R131 R132 R133 R134 R135 R136 R137 R138 R139 R140 R141 R142 R143 R144 R145 R146 R147 R148 R149 R150 R151 R152 R153 R154 R155 R156 R157 R158 R159 R160 R161 R162 R163 R164 R165 R166 R167 R168 R169 R170 R171 R172 R173 R174 R175 R176 R177 R178 R179 R180 R181 R182 R183 R184 R185 R186 R187 R188 R189 R190 R191 R192 R193 R194 R195 R196 R197 R198 R199 R200 R201 R202 R203 R204 R205 R206 R207 R208 R209 R210 R211 R212 R320 R321 R322 R323 R324 R325 R326 R327 R328 R329 R330 R331 U25 U26 U27 U28 U29 U30
component class TIDA-010948-CB-PRUIO_CLKGEN: 30 C53 C54 C55 C56 C57 C58 C59 C60 C61 C62 C63 C64 C65 C66 L3 L4 L5 NT4 R107 R108 R109 R110 R111 R112 R113 R114 R115 R116 R117 R118 R119 R120 R121 R122 R123 R124 R125 R126 R127 R128 R236 R318 R319 TP23 TP24 TP25 TP26 TP27 TP28 TP29 TP30 U21 U22 U23 U24 Y1
component class TIDA-010948-CB-Power: C1 C2 C3 C4 C5 C6 C7 C8 C9 C10 C11 C12 C13 C14 C15 C16 C17 C18 C19 C20 C21 C22 C23 C24 C25 C26 C27 C168 C174 D1 D2 D3 D4 D5 J1 L1 L2 L12 MD1 NT1 NT2 Q1 Q2 Q3 R1 R2 R3 R4 R5 R6 R7 R8 R9 R10 R11 R12 R13 R14 R15 R16 R17 R18 R19 R20 R21 R22 R23 R24 R25 R26 TP1 TP2 TP3 TP4 TP5 TP6 TP7 TP8 TP9 TP34 TP40 TP41 U1 U2 U3 U4 U5 U6
component class TIDA-010948-CB-Interface: C177 C193 C194 C195 C196 C197 C198 C199 C200 C201 C202 C203 C204 C205 C206 D20 D21 D22 J11 J12 J13 J14 R292 R293 R294 R295 R296 R297 R298 R299 R300 R301 R302 R303 R311 R312 R313 R314 R315 R316 R332 R333 R334 R335 R336 R337 R338 R339 R340 R341 R342 R343 TP37 TP38 TP39 U41 U42 U43 U44 U45 U46
component class TIDA-010948-CB-Ethernet2: C151 C152 C153 C155 C156 C157 C158 C159 C160 C161 C163 C164 C165 C166 C167 C169 C170 C171 C172 C173 C175 C176 C178 C179 C180 C181 C182 C183 C184 C185 C186 C187 C188 C189 C190 C191 D16 D17 D18 D19 J9 L9 L10 L11 Q6 Q7 R247 R253 R254 R255 R256 R257 R258 R259 R260 R261 R262 R263 R264 R265 R266 R267 R269 R270 R271 R272 R273 R274 R275 R277 R278 R279 R280 R282 R283 R284 R285 R286 R287 R288 R289 R290 T2 TP15 TP16 TP17 TP18 TP19 TP35 TP36 U36 U37 U38 U39 U40
component class TIDA-010948-CB-Ethernet1: C109 C110 C111 C113 C114 C115 C116 C117 C118 C119 C121 C122 C123 C124 C125 C127 C128 C129 C130 C131 C133 C134 C136 C137 C138 C139 C140 C141 C142 C143 C144 C145 C146 C147 C148 C149 C150 D12 D13 D14 D15 J7 J8 L6 L7 L8 Q4 Q5 R213 R214 R215 R216 R217 R218 R219 R221 R222 R223 R224 R225 R226 R227 R228 R229 R230 R231 R232 R233 R234 R235 R237 R238 R239 R240 R242 R243 R244 R245 R246 R248 R249 R250 R251 R252 R305 T1 TP10 TP11 TP12 TP14 TP31 TP32 TP33 U31 U32 U33 U34 U35
component class TIDA-010948-CB-Debug: C34 C35 C36 C37 C38 C39 C40 C41 C42 C43 C44 C45 C46 C135 D6 D7 D8 D9 D10 D11 J2 J3 J4 J5 J6 J15 R61 R62 R63 R64 R65 R66 R67 R68 R69 R70 R71 R72 R73 R74 R75 R76 R77 R78 R79 R80 R81 R82 R83 R84 R85 R86 R87 R88 R89 R90 R91 R92 R93 R94 R220 R304 R306 R307 R308 R309 R310 S1 TP13 TP21 TP22 U12 U13 U14 U15 U16 U17
component class TIDA-010948-CB-Bootmode: C28 C29 C30 C31 C32 C33 R27 R28 R29 R30 R31 R32 R33 R34 R35 R36 R37 R38 R39 R40 R41 R42 R43 R44 R45 R46 R47 R48 R49 R50 R51 R52 R53 R54 R55 R56 R57 R58 R59 R60 SW1 SW2 SW3 SW4 TP20 U7 U8 U9 U10 U11
net class GPMC_AD[0..15]: GPMC_AD0 GPMC_AD1 GPMC_AD2 GPMC_AD3 GPMC_AD4 GPMC_AD5 GPMC_AD6 GPMC_AD7 GPMC_AD8 GPMC_AD9 GPMC_AD10 GPMC_AD11 GPMC_AD12 GPMC_AD13 GPMC_AD14 GPMC_AD15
